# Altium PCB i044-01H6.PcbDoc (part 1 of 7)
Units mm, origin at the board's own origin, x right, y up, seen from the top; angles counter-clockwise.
Board outline 42 x 29.01 mm, 8 copper layers (Top Layer, Mid-Layer 1, Mid-Layer 2, Mid-Layer 3, Mid-Layer 4, Mid-Layer 5, Mid-Layer 6, Bottom Layer), stack 1.474 mm thick; 235 components, 197 nets, 1006 pads, 1183 vias.
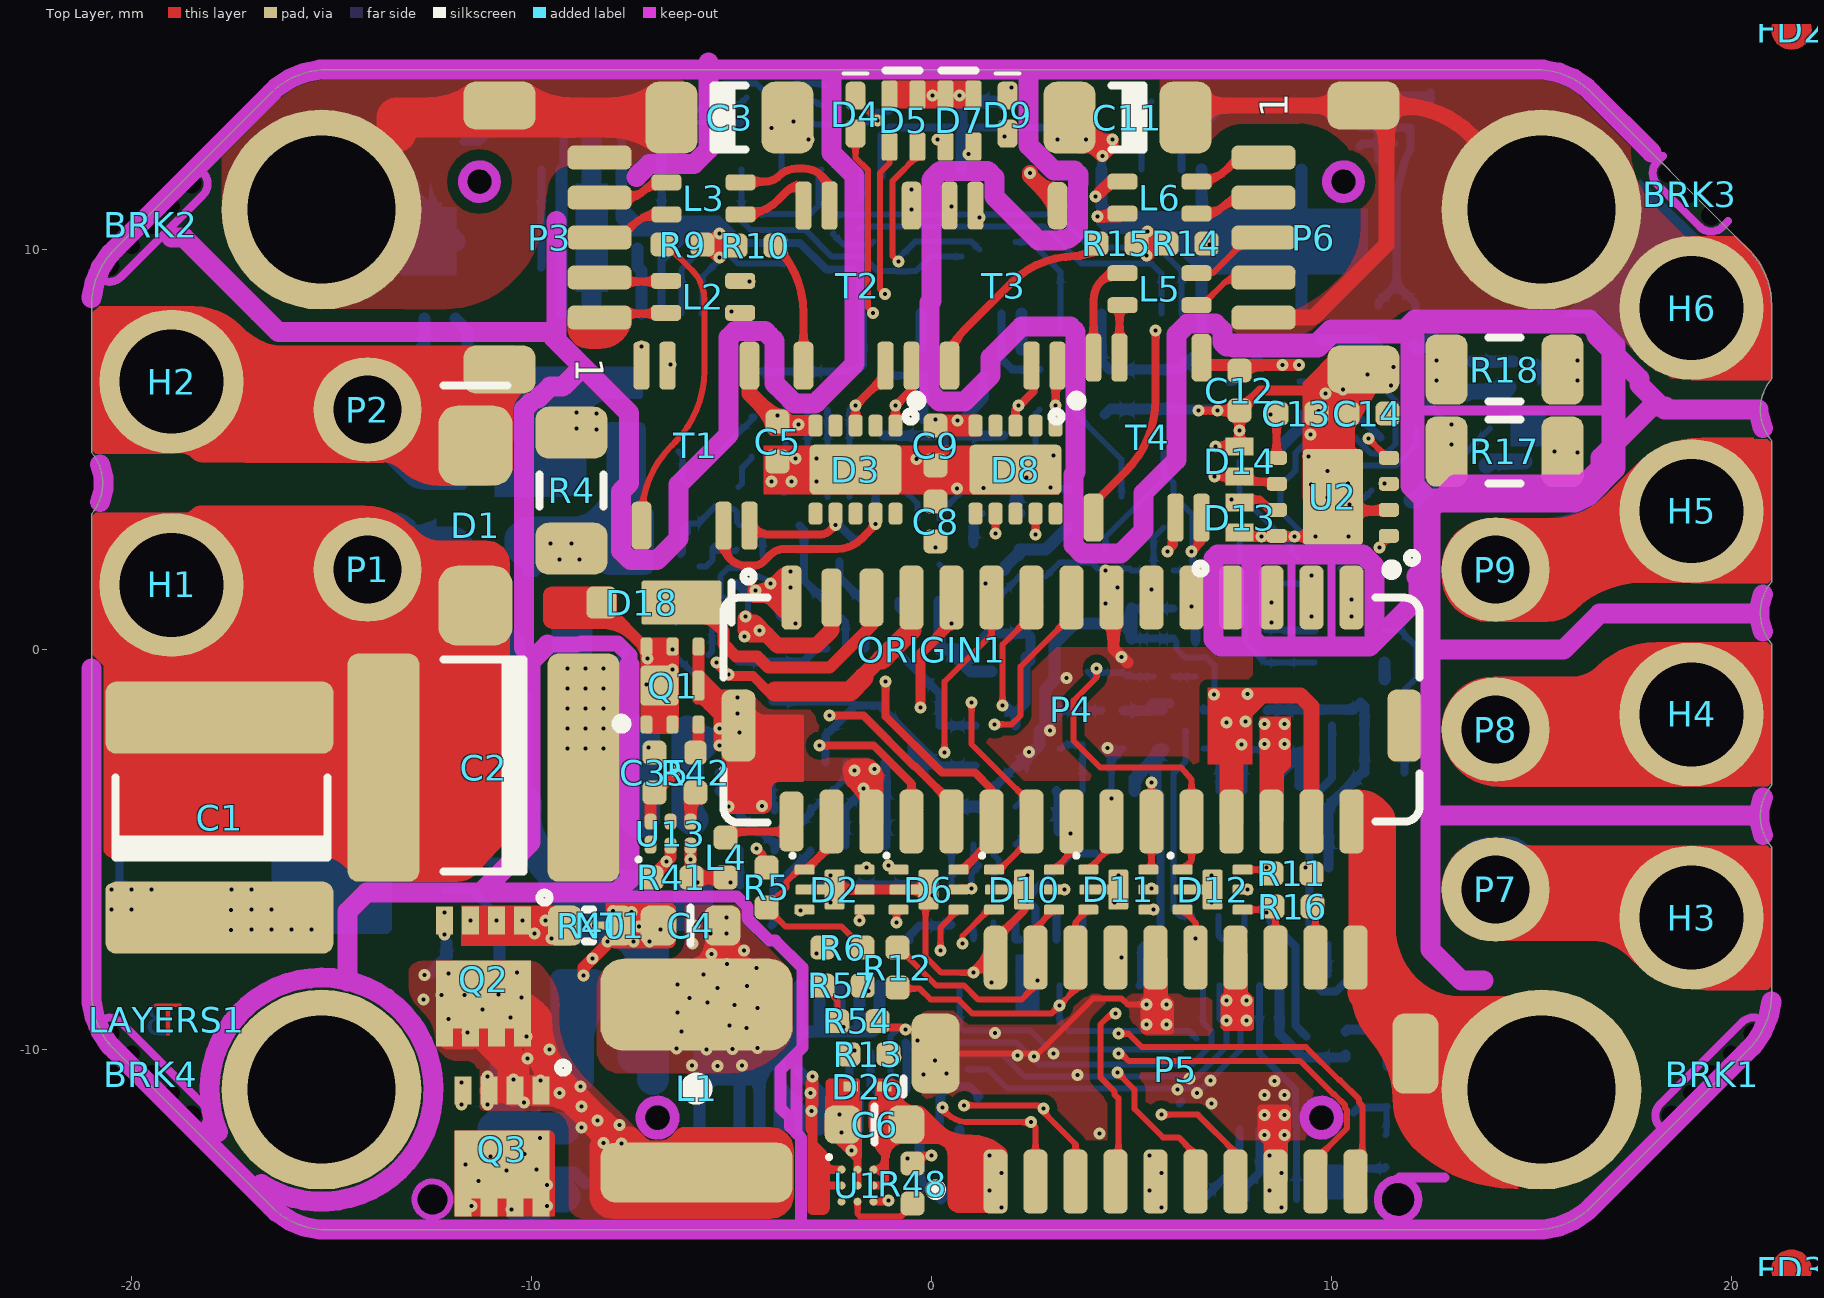
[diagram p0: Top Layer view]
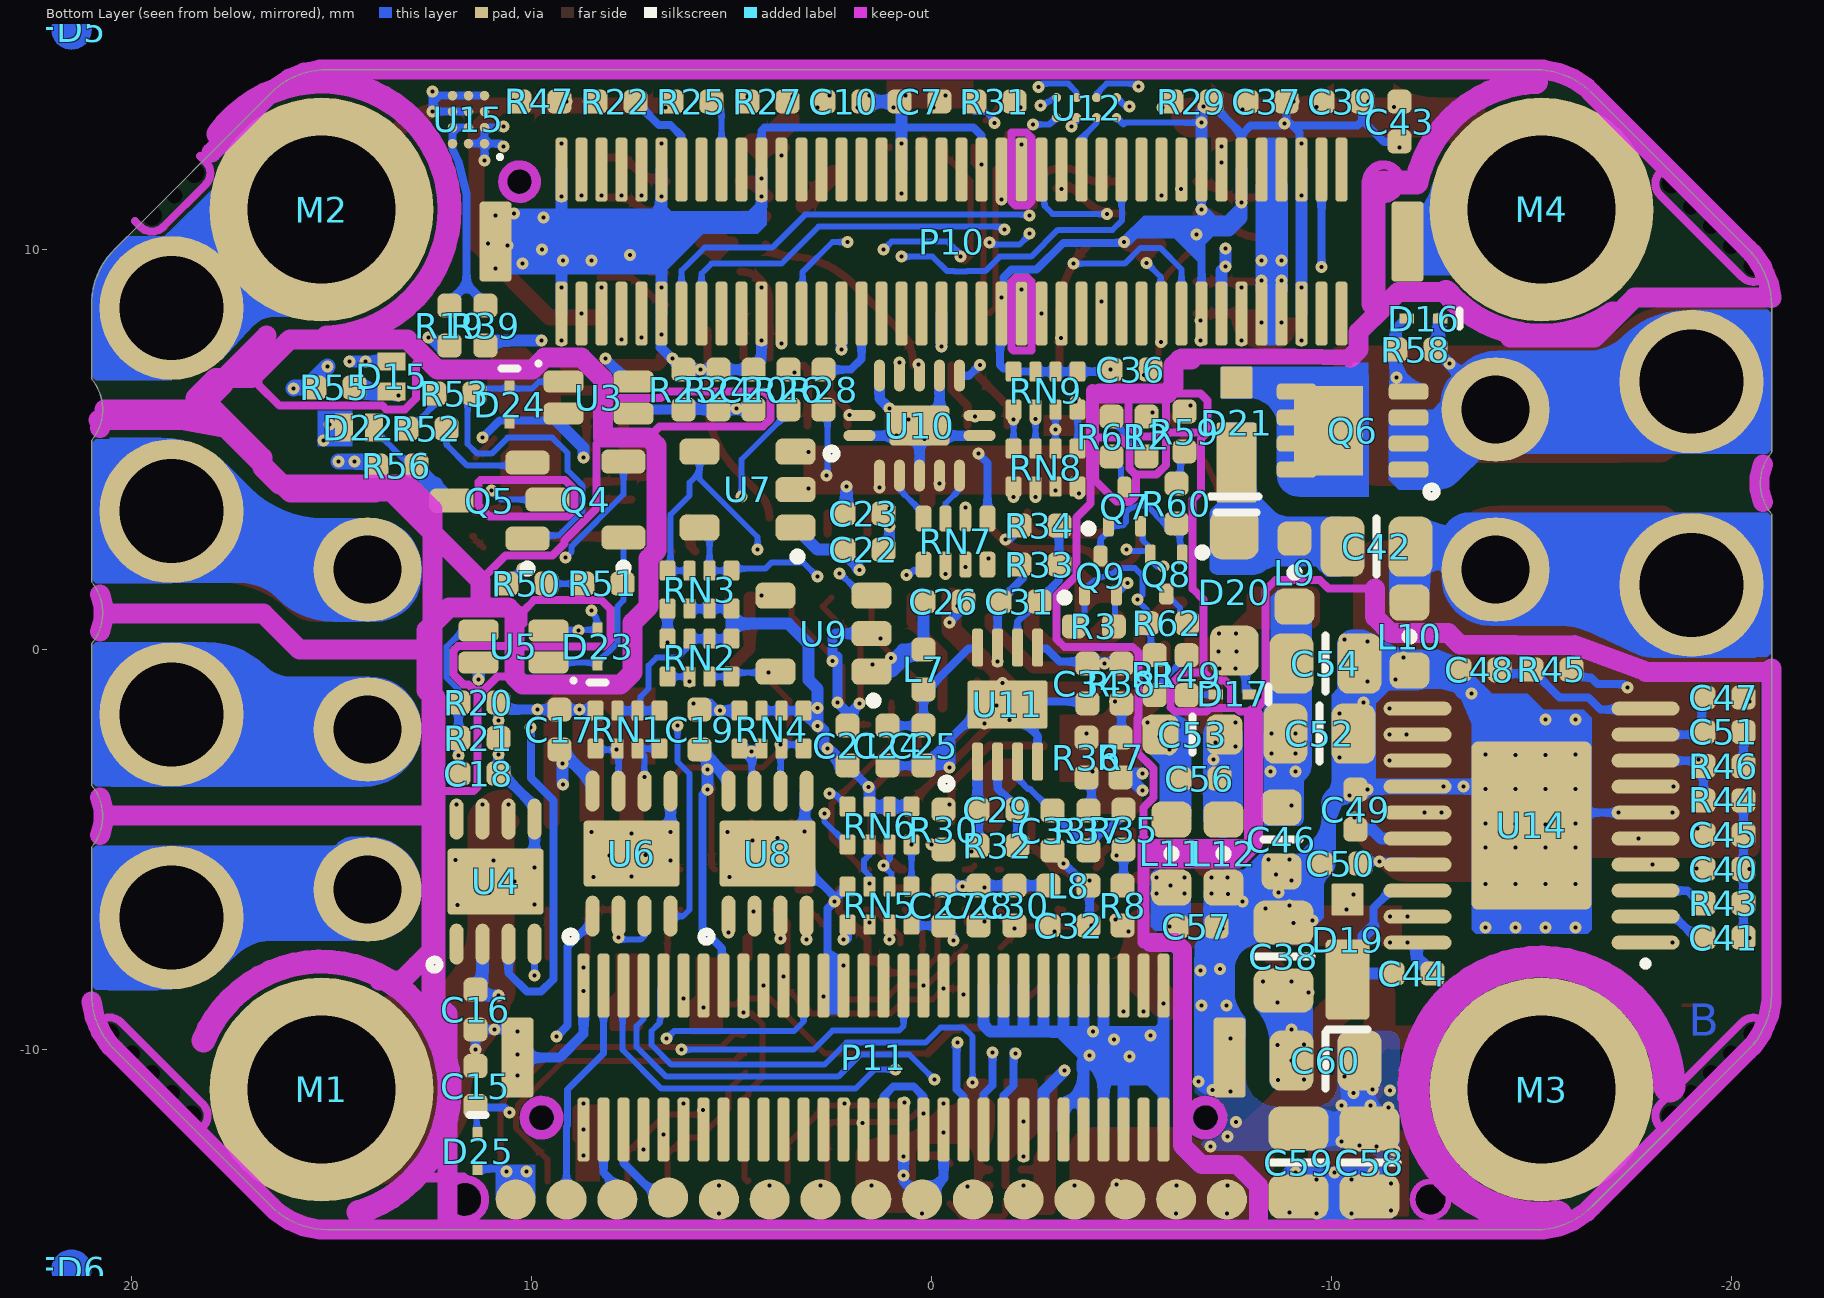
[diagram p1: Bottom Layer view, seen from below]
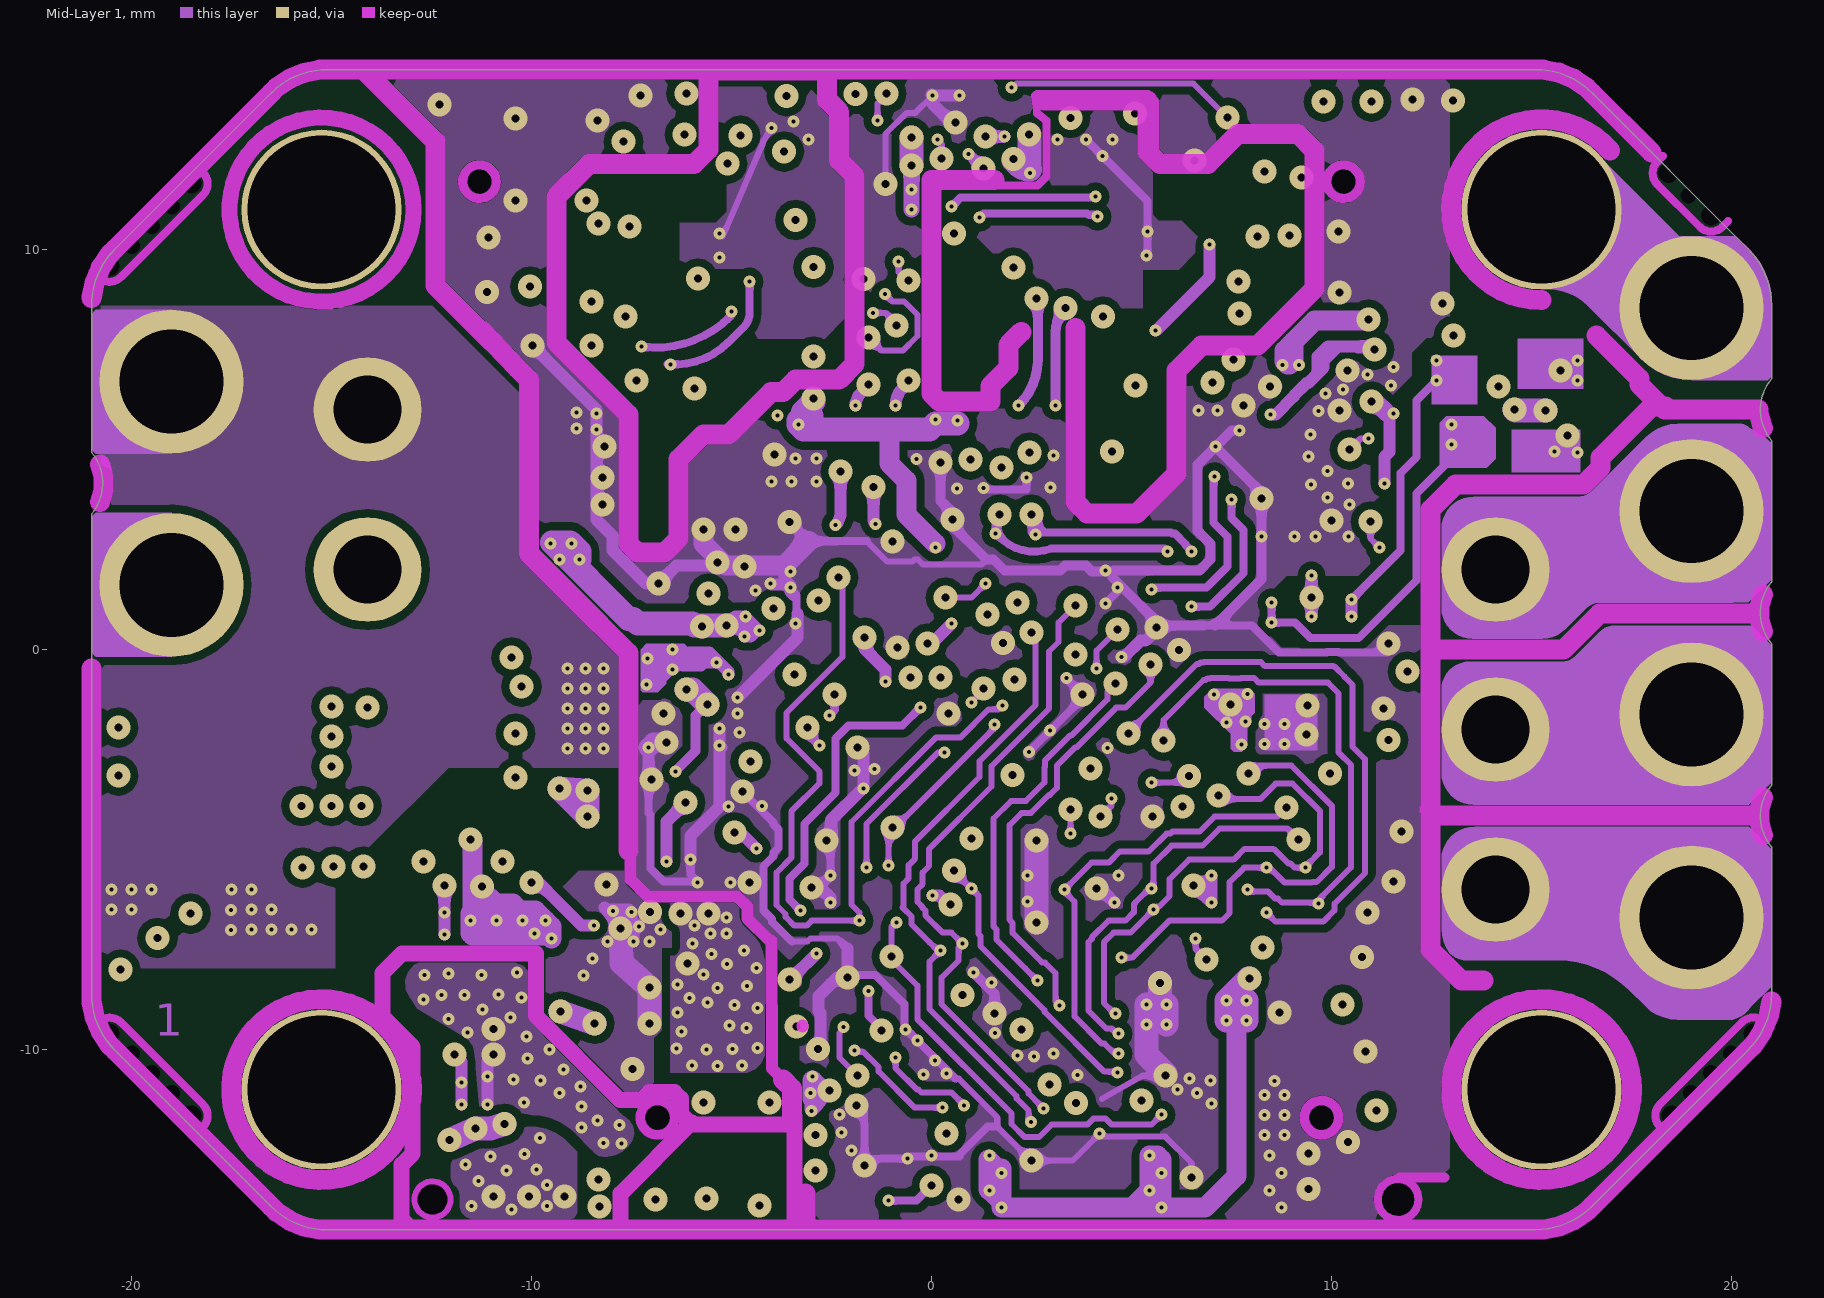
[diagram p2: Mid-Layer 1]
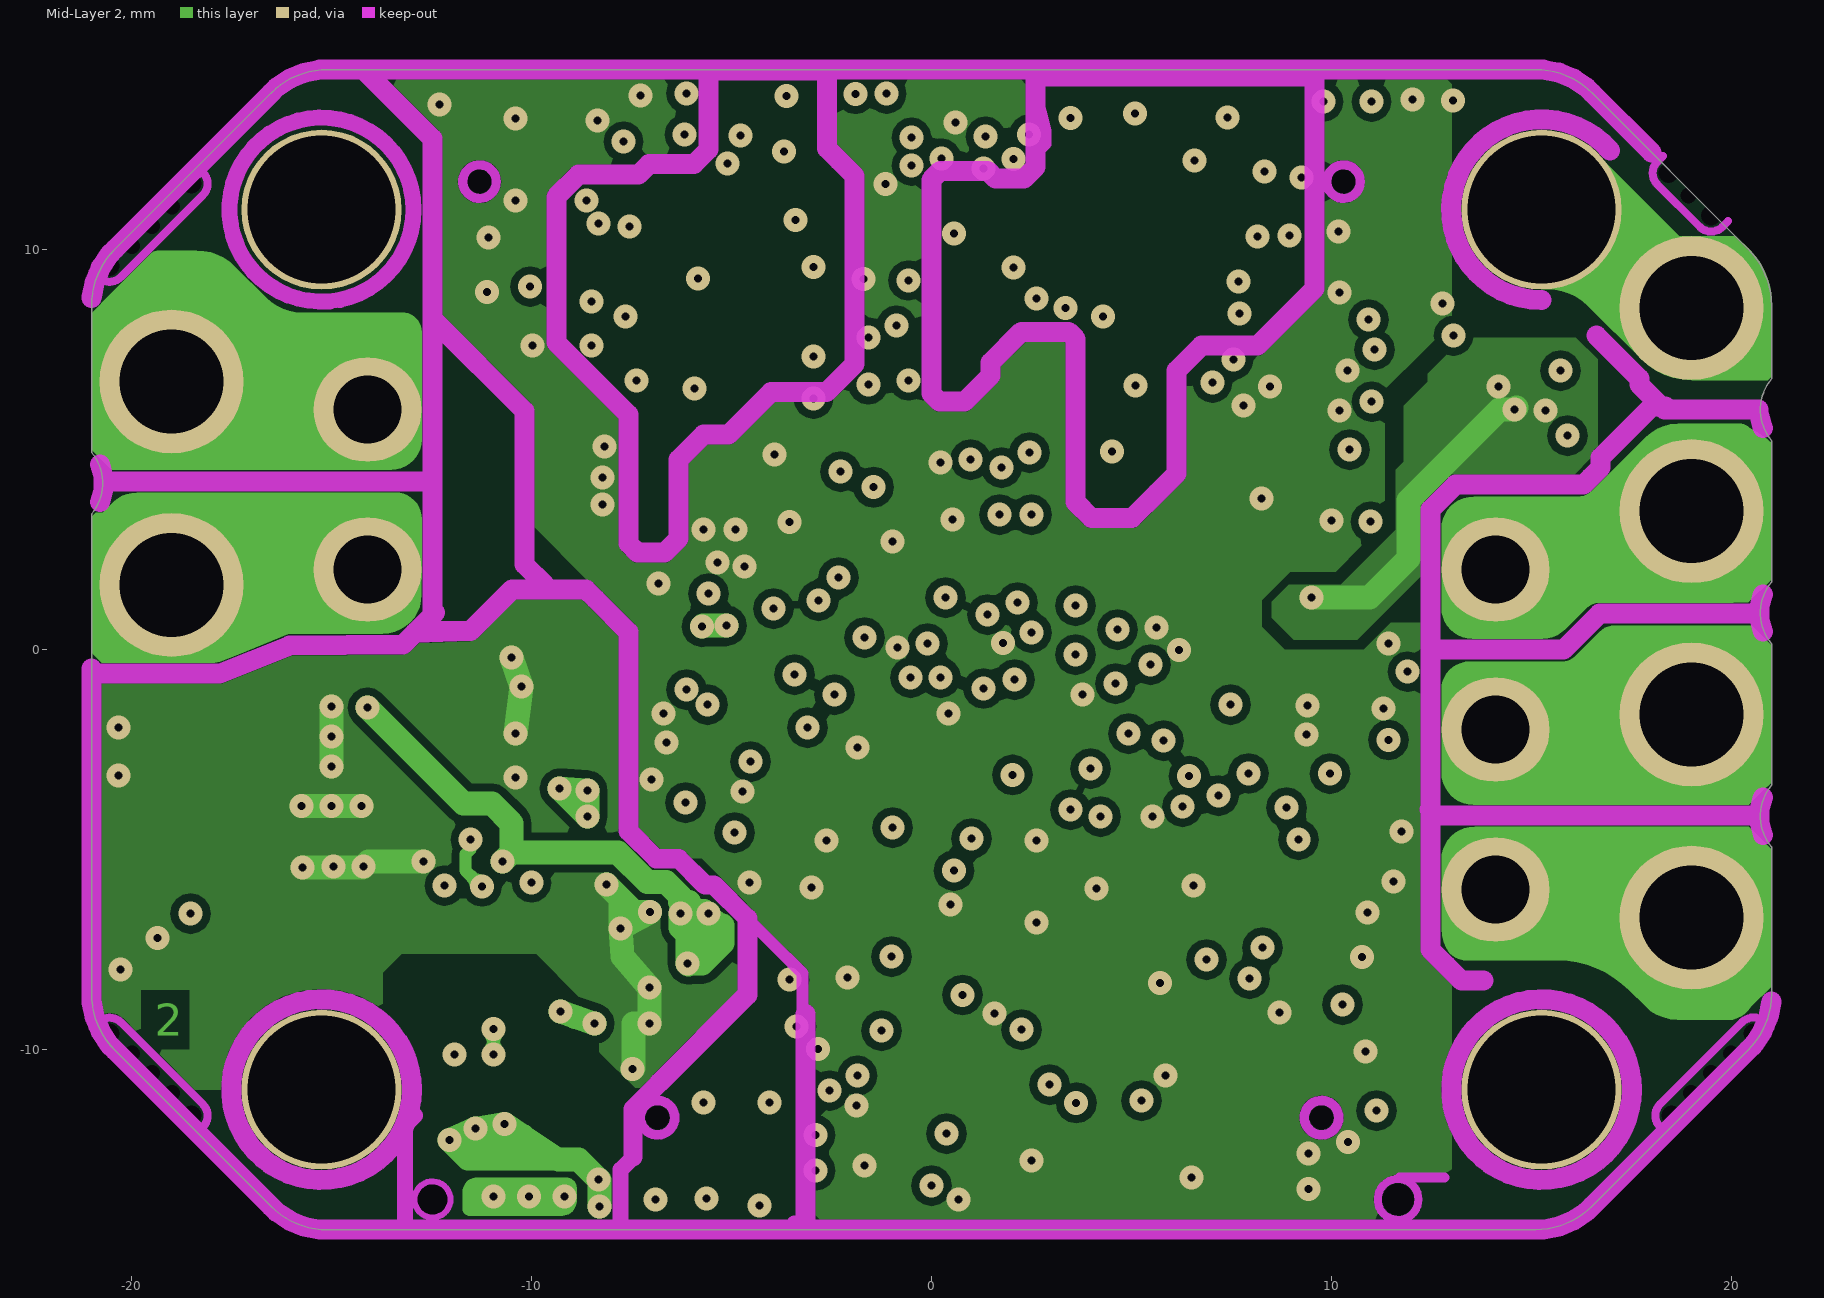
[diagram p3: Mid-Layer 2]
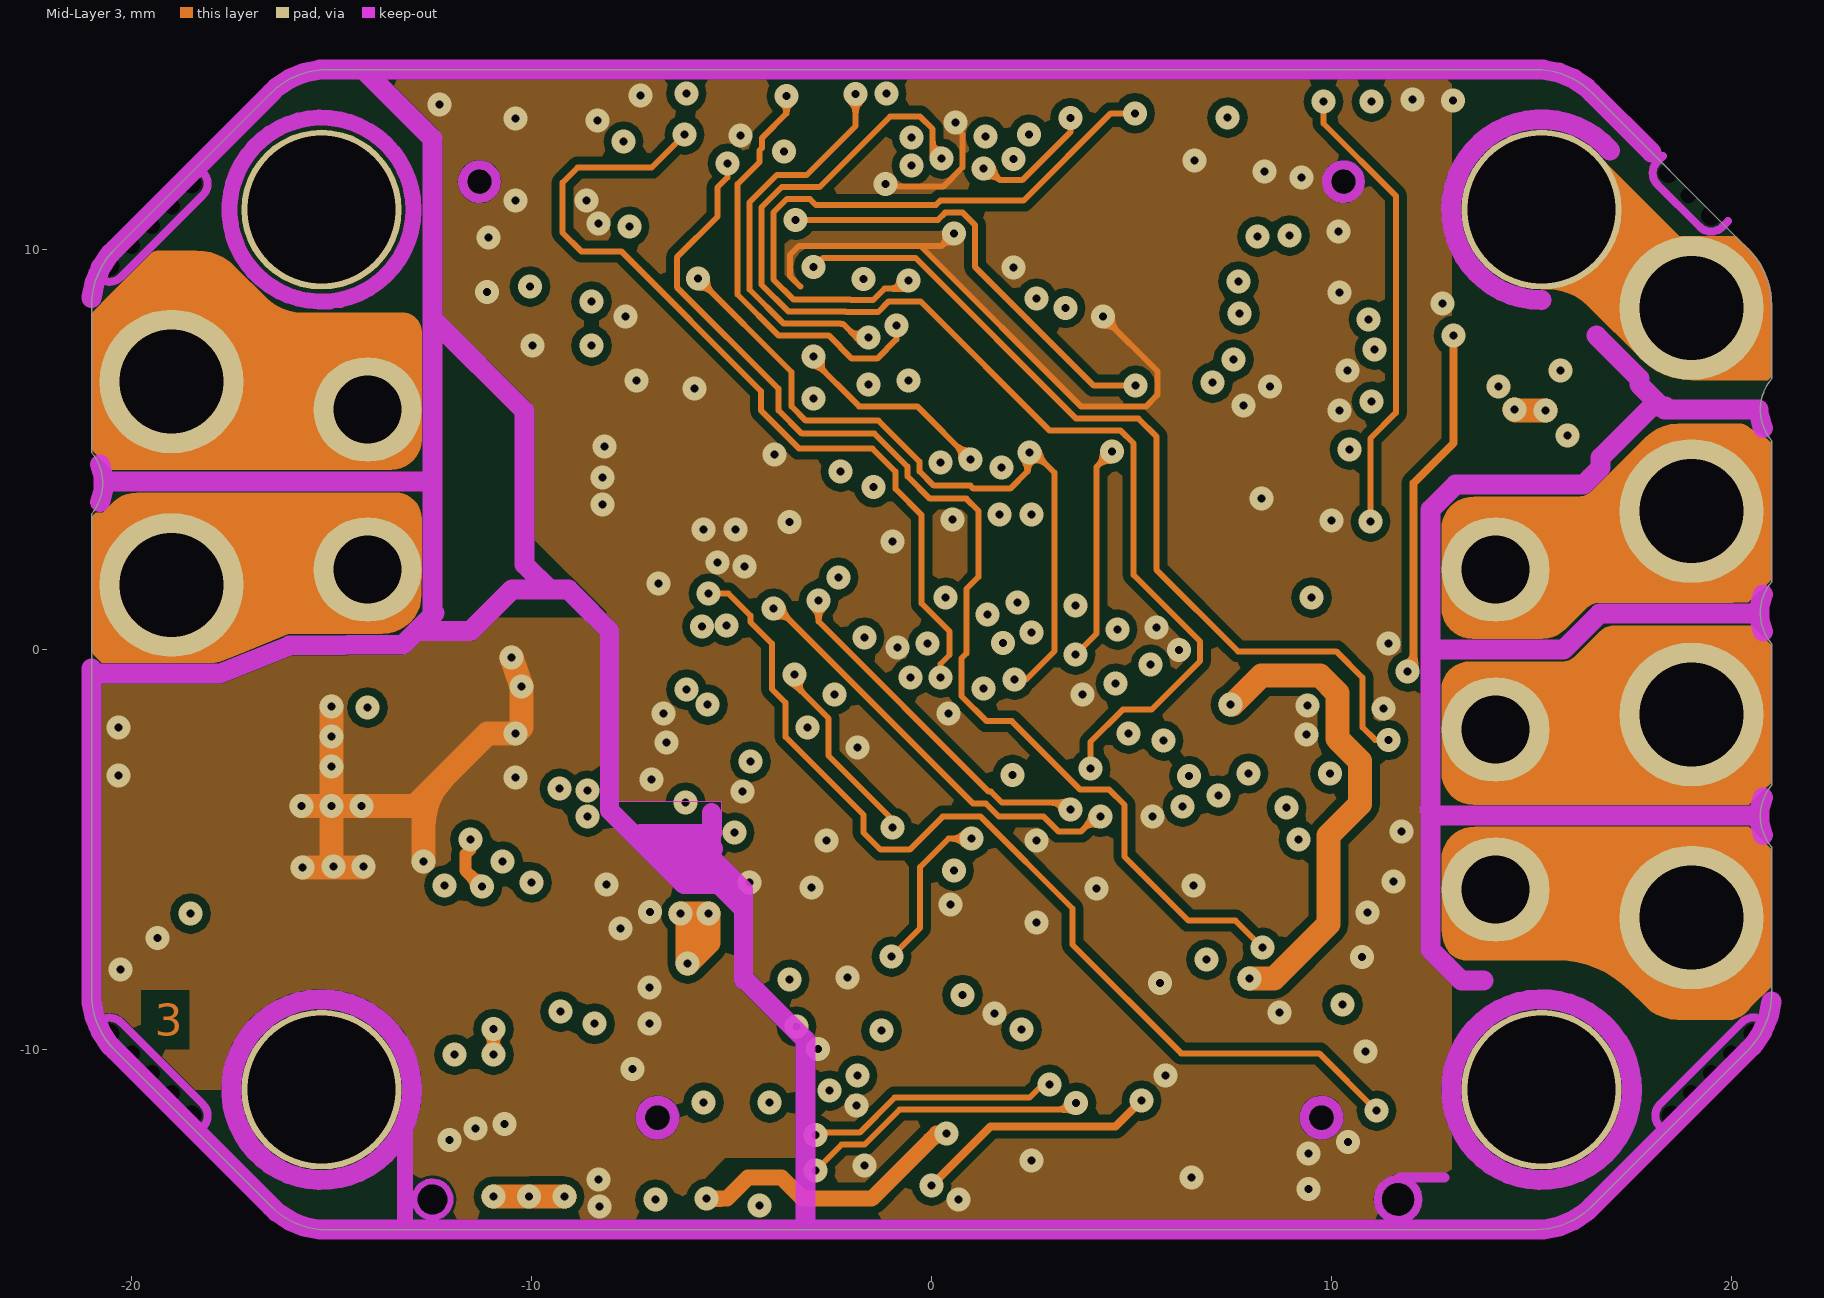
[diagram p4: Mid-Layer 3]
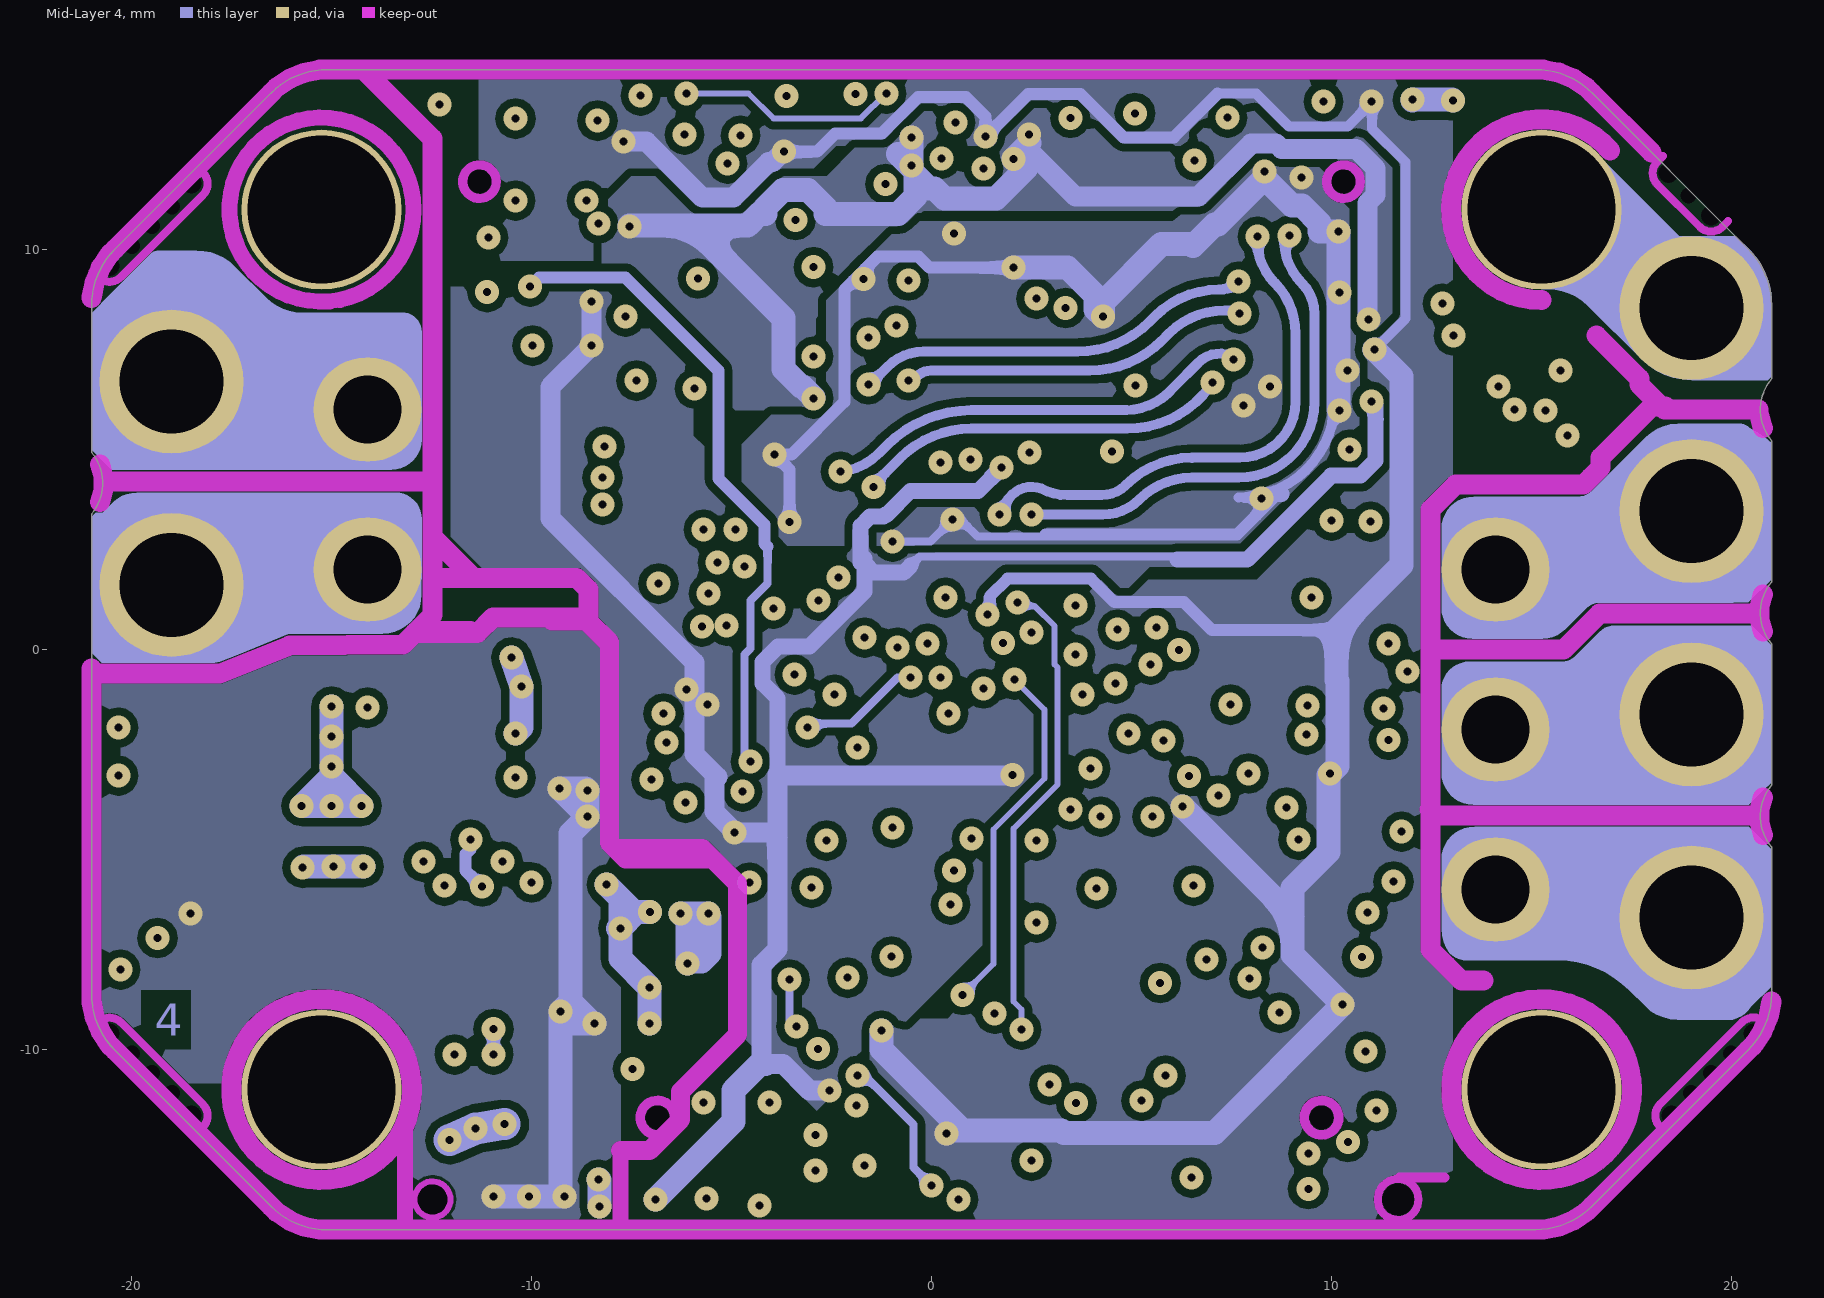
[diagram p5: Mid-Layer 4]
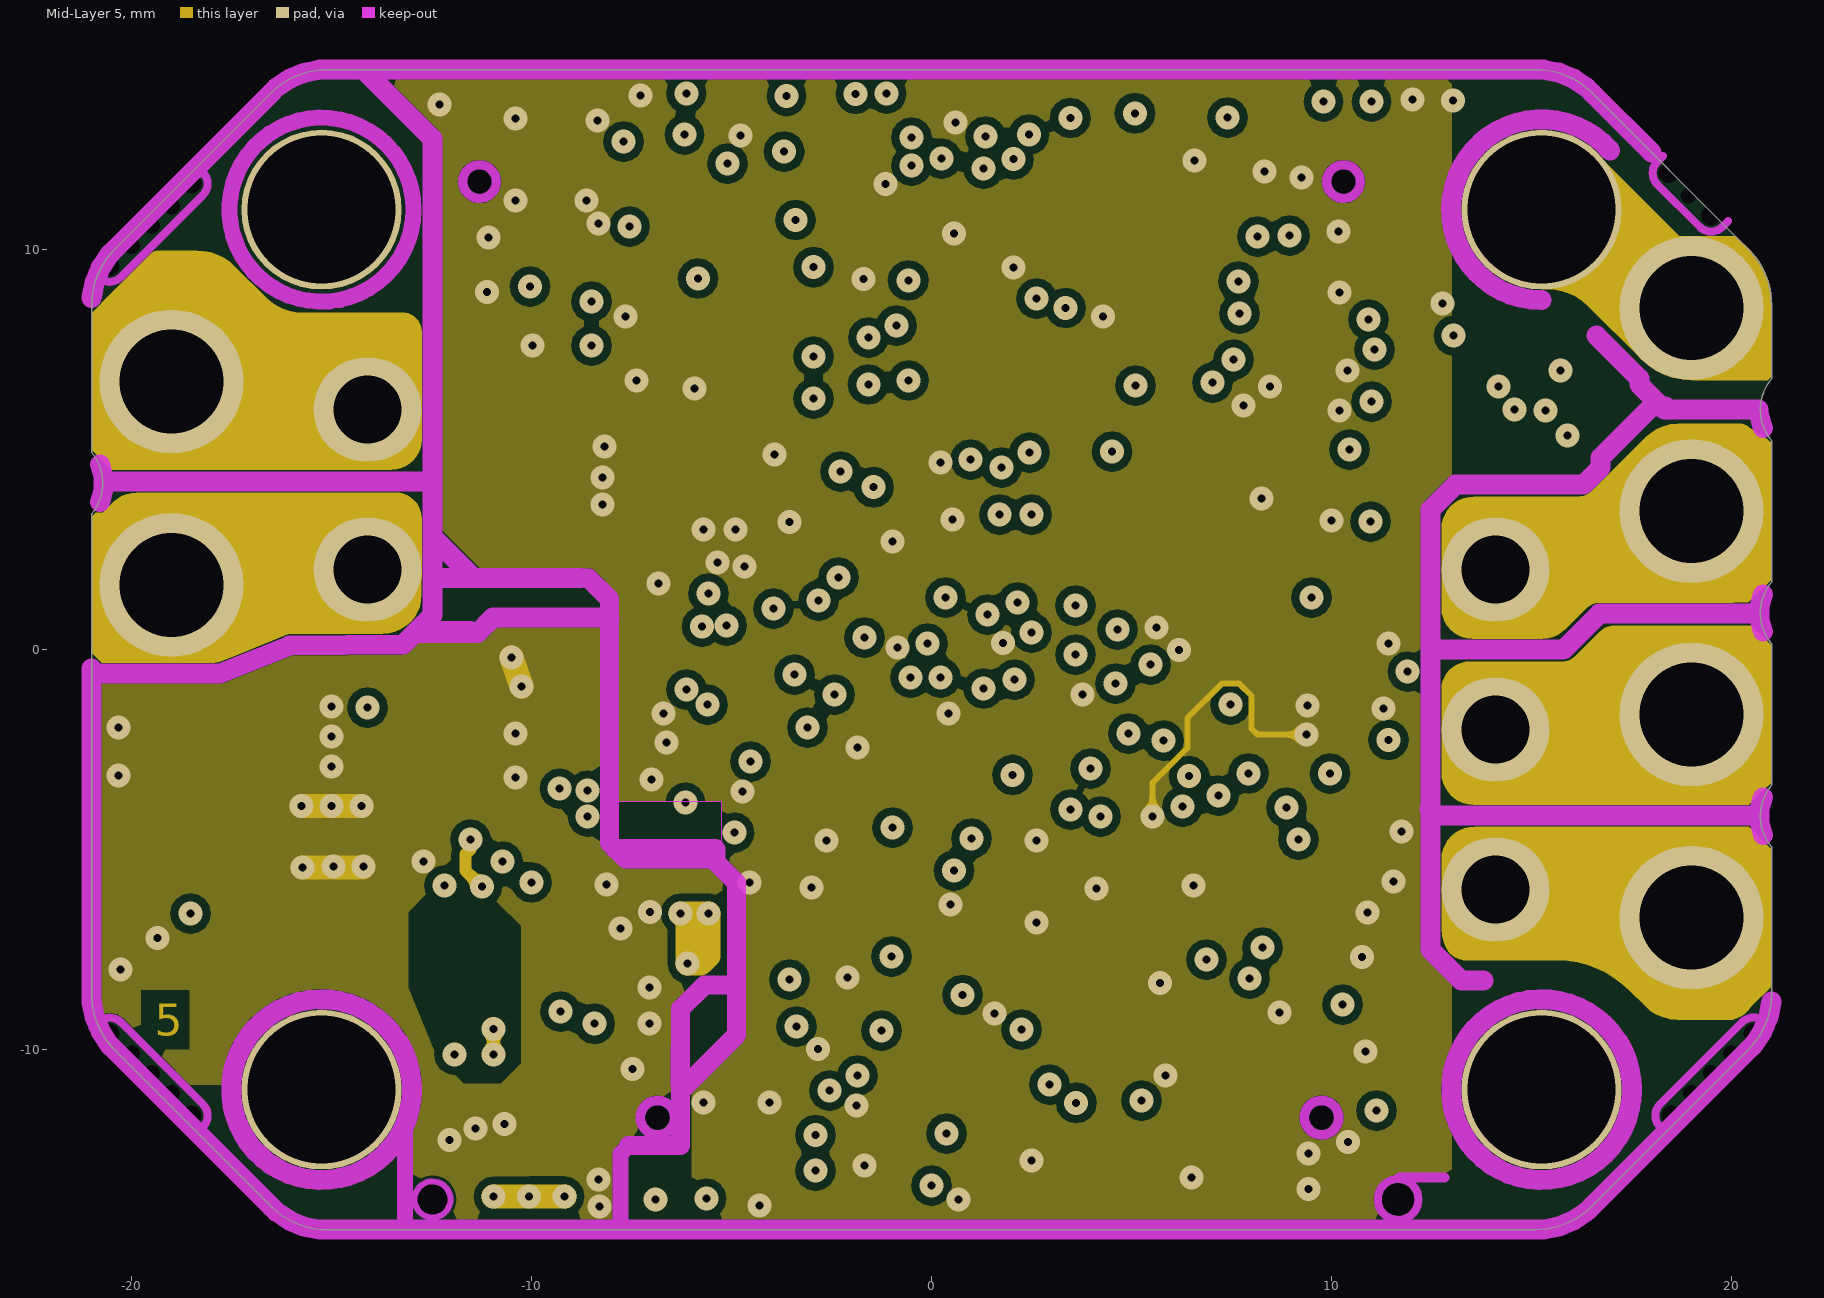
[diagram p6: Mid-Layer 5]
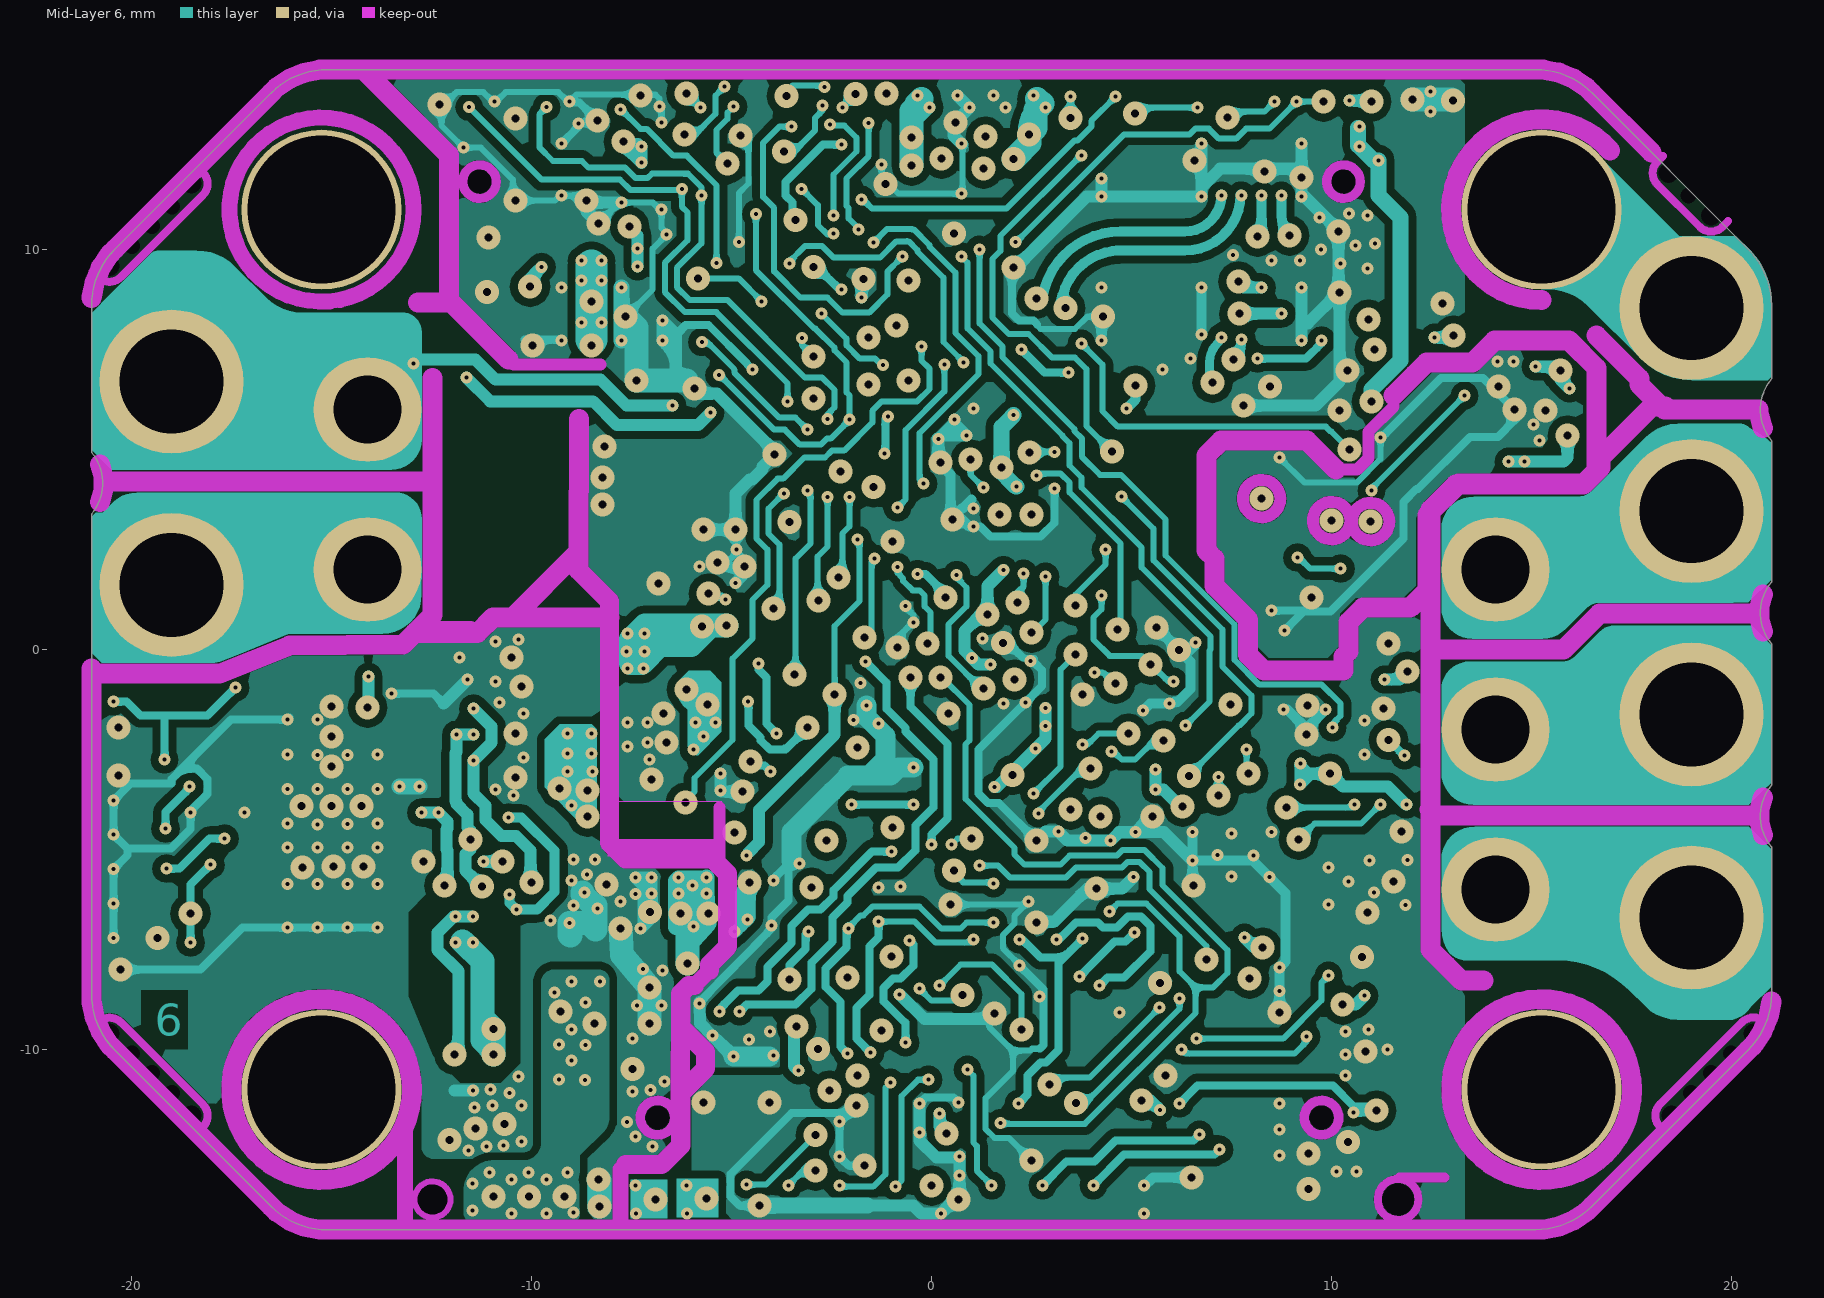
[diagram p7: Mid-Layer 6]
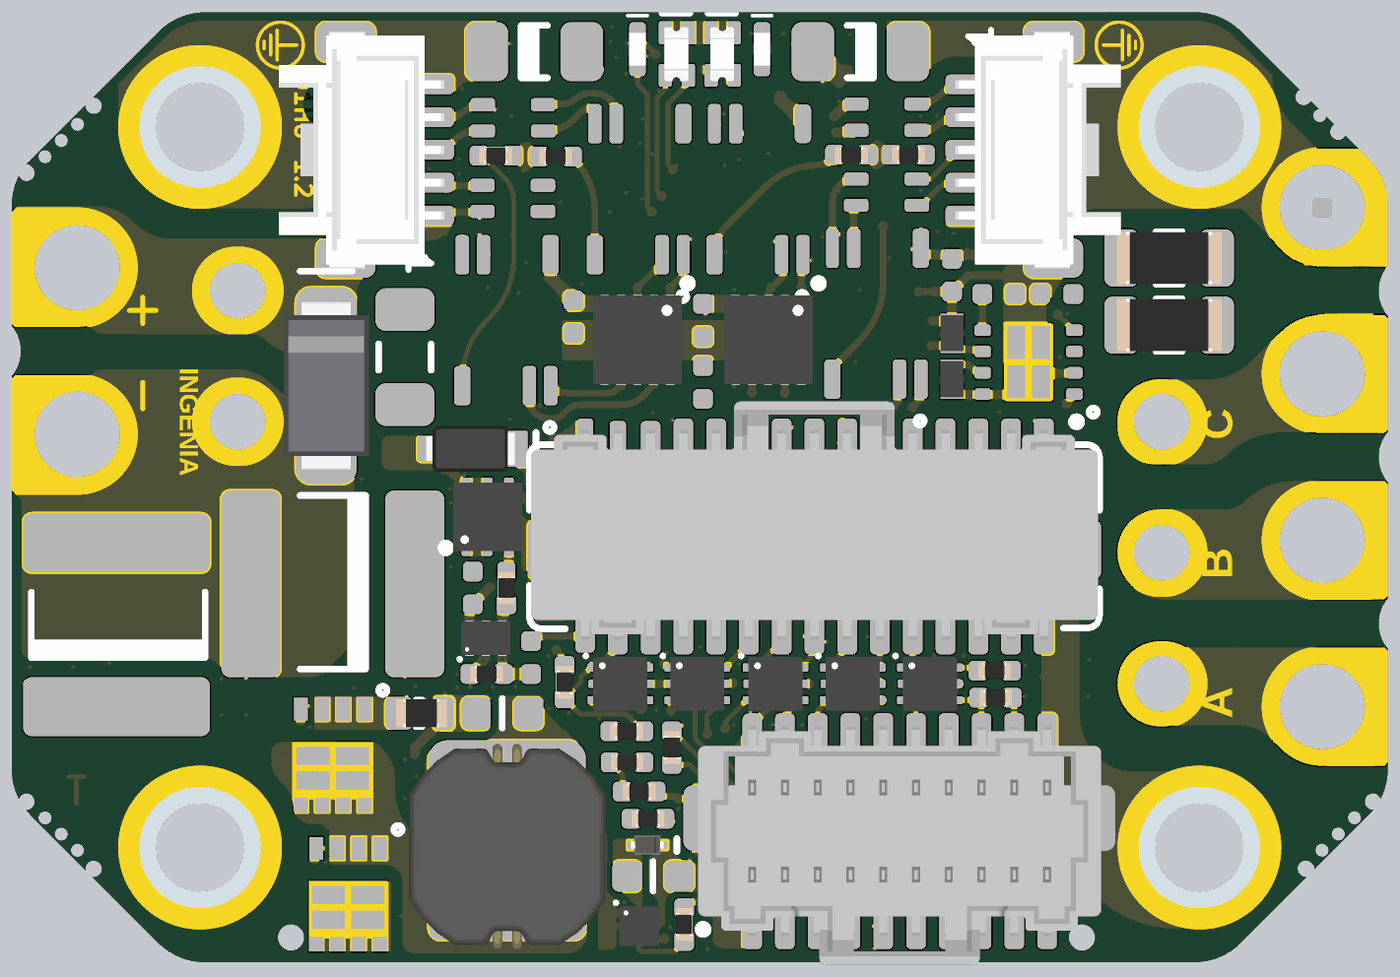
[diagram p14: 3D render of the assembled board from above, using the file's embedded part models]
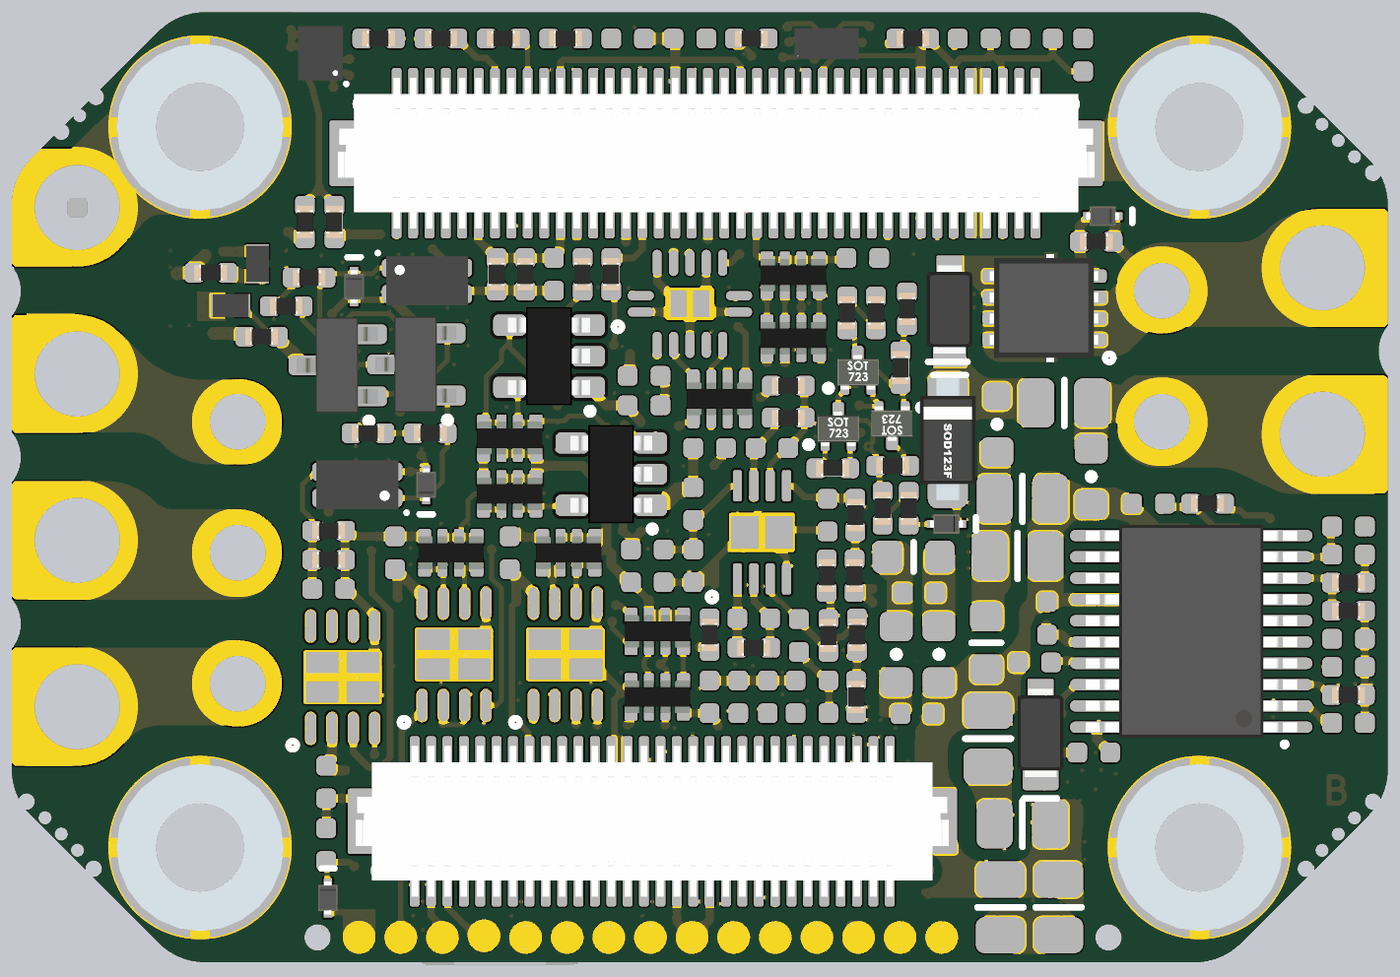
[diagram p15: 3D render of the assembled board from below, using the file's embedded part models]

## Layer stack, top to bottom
Top Solder: solder mask 0.005, Solder Resist, Dk 3.5
Top Layer: signal copper 0.042
Dielectric 1: prepreg 0.1, FR-4 (tg > 150 Celsius), Dk 4.2
Mid-Layer 1: signal copper 0.035
Dielectric 2: core 0.24, FR-4 (tg > 150 Celsius), Dk 4.2
Mid-Layer 2: signal copper 0.035
Dielectric 3: prepreg 0.13, FR-4 (tg > 150 Celsius), Dk 4.2
Mid-Layer 3: signal copper 0.035
Dielectric 4: core 0.24, FR-4 (tg > 150 Celsius), Dk 4.2
Mid-Layer 4: signal copper 0.035
Dielectric 5: prepreg 0.13, FR-4 (tg > 150 Celsius), Dk 4.2
Mid-Layer 5: signal copper 0.035
Dielectric 6: core 0.24, FR-4 (tg > 150 Celsius), Dk 4.2
Mid-Layer 6: signal copper 0.035
Dielectric 7: prepreg 0.1, FR-4 (tg > 150 Celsius), Dk 4.2
Bottom Layer: signal copper 0.042
Bottom Solder: solder mask 0.005, Solder Resist, Dk 3.5

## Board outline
-20.414,-10.017 -16.516,-13.917 ccw(c-15.102,-12.503) -15.102,-14.503 -15.1,-14.502 15.1,-14.498 ccw(c15.1,-12.498) 16.514,-13.913 20.414,-10.014 ccw(c19,-8.6) 21,-8.6 21,-4.933 cw(c21.919,-4.161) 21,-3.39 21,0.147 cw(c21.919,0.919) 21,1.69 21,5.227 cw(c21.919,5.999) 21,6.77 21,8.603 ccw(c19,8.603) 20.414,10.017 16.517,13.915 16.516,13.917 ccw(c15.102,12.503) 15.102,14.503 15.1,14.502 -15.1,14.498 ccw(c-15.1,12.498) -16.514,13.913 -20.414,10.014 ccw(c-19,8.6) -21,8.6 -21,4.932 cw(c-21.919,4.161) -21,3.389 -21,-8.603 ccw(c-19,-8.603)

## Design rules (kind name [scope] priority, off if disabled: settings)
AssemblyTestPointUsage [All] p1 off: valid=2
AssemblyTestpoint [All] p1 off: testpointundercomponent=TRUE minsize=1.016 maxsize=2.54 preferedsize=1.524 minholesize=0 maxholesize=1.016 preferedholesize=0.813 testpointgrid=0.025 usegrid=TRUE gridtolerance=0 allowsidetop=TRUE allowsidebottom=TRUE
Clearance Clearance_BreakAway [HasFootprint('BREAKAWAY_VIAS_3.4MM') Or HasFootprint('BREAKAWAY_VIAS_2MM')] p1: gap=0.01 ignorepadtopadclearanceinfootprint=TRUE
Clearance "Keepout clearance" [All vs OnLayer('Keep-Out Layer') Or IsKeepOut Or Keepout] p2: gap=0.001 ignorepadtopadclearanceinfootprint=FALSE
Clearance HV_Logic_Supply [InNet('+LOG_SUP')] p3: gap=0.2 ignorepadtopadclearanceinfootprint=TRUE
Clearance HV [InNetClass('HighVoltage') vs OnOutside And NOT InNetClass('HighVoltageFloating')] p4: gap=0.5 ignorepadtopadclearanceinfootprint=TRUE
Clearance Clearance_PE [InNetClass('ProtectiveEarth')] p5: gap=0.5 ignorepadtopadclearanceinfootprint=TRUE
Clearance Clearance_Poly [InPoly] p6: gap=0.2 ignorepadtopadclearanceinfootprint=FALSE
Clearance General [All] p7: gap=0.15 ignorepadtopadclearanceinfootprint=TRUE
ComponentClearance PowerPads_Clearance [HasFootprint('PAD_1.65MMTH')] p1: gap=0 collisioncheckmode=3 verticalgap=0 showdistances=FALSE donotcheckwithout3dbody=TRUE
ComponentClearance Fastene_Clearance [IsFree And OnLayer('Mechanical 1')] p2: gap=0 collisioncheckmode=3 verticalgap=0 showdistances=FALSE donotcheckwithout3dbody=TRUE
ComponentClearance Origin_Clearance [HasFootprint('ORIGIN')] p3: gap=0 collisioncheckmode=3 verticalgap=0 showdistances=FALSE donotcheckwithout3dbody=TRUE
ComponentClearance [All] p4: gap=0.2 collisioncheckmode=3 verticalgap=0.2 showdistances=FALSE donotcheckwithout3dbody=TRUE
DiffPairsRouting [All] p1: maxlimit=1 minlimit=0.15 mostfreqgap=0.2 toplayer_minwidth=0.15 toplayer_maxwidth=0.3 toplayer_prefwidth=0.2 midlayer1_minwidth=0.15 midlayer1_maxwidth=0.3 midlayer1_prefwidth=0.2 midlayer2_minwidth=0.15 midlayer2_maxwidth=0.3 midlayer2_prefwidth=0.2 midlayer3_minwidth=0.15 midlayer3_maxwidth=0.3 midlayer3_prefwidth=0.2 midlayer4_minwidth=0.15 midlayer4_maxwidth=0.3 midlayer4_prefwidth=0.2 midlayer5_minwidth=0.15 midlayer5_maxwidth=0.3 midlayer5_prefwidth=0.2 midlayer6_minwidth=0.15 midlayer6_maxwidth=0.3 midlayer6_prefwidth=0.2 bottomlayer_minwidth=0.15 bottomlayer_maxwidth=0.3 bottomlayer_prefwidth=0.2 maxuncoupledlength=12.7
FabricationTestPointUsage [All] p1 off: valid=0 allowmultiple=FALSE
FabricationTestpoint [All] p1 off: side=3 testpointundercomponent=TRUE minsize=1.016 maxsize=2.54 preferedsize=1.524 minholesize=0 maxholesize=1.016 preferedholesize=0.813 testpointgrid=0.025 allowsidetop=TRUE allowsidebottom=TRUE usegrid=TRUE gridtolerance=0
FanoutControl Fanout_BGA [IsBGA] p1 off: bgadir=Out bgaviamode=Centered fanoutstyle=Auto fanoutdirection=Alternating viagrid=0.025 // Fanout_BGA (Default Rule)
FanoutControl Fanout_LCC [IsLCC] p2 off: bgadir=Out bgaviamode=Centered fanoutstyle=Auto fanoutdirection=Alternating viagrid=0.025 // Fanout_LCC (Default Rule)
FanoutControl Fanout_SOIC [IsSOIC] p3 off: bgadir=Out bgaviamode=Centered fanoutstyle=Auto fanoutdirection=Alternating viagrid=0.025 // Fanout_SOIC (Default Rule)
FanoutControl Fanout_Small [(CompPinCount < 5)] p4 off: bgadir=Out bgaviamode=Centered fanoutstyle=Auto fanoutdirection=OutThenIn viagrid=0.025 // Fanout_Small (Default Rule)
FanoutControl Fanout_Default [All] p5 off: bgadir=Out bgaviamode=Centered fanoutstyle=Auto fanoutdirection=Alternating viagrid=0.025 // Fanout_Default (Default Rule)
Height [All] p1: minheight=0 maxheight=30 prefheight=12.7
HoleSize [All] p1: absolutevalues=TRUE maxlimit=5 minlimit=0.1 maxpercent=80.000 minpercent=20.000
HoleToHoleClearance [All] p1: gap=0.3 allowstackedmicrovias=FALSE
MinimumAnnularRing [All] p1: minimumring=0.1
MinimumSolderMaskSliver [All] p1: minsoldermaskwidth=0.07
NetAntennae [All] p1: netantennaetolerance=2
PlaneClearance [All] p1: clearance=0.25
PlaneConnect [All] p1: planeconnectstyle=Relief reliefexpansion=0.5 reliefentries=4 reliefconductorwidth=0.25 reliefairgap=0.25
PolygonConnect [All] p1: connectstyle=Direct reliefconductorwidth=0.25 reliefentries=4 polygonreliefangle="90 Angle" airgapwidth=0.25
RoomDefinition U_M_PXE032_HD_Diff-SE_Digital_Abs_Encoder_WBias_WTerm [InComponentClass('U_M_PXE032_HD_Diff-SE_Digital_Abs_Encoder_WBias_WTerm')] p1 off: confinementstyle=ConfineIn formatcopy=TRUE lockcomponents=FALSE outline 22.12,-5.98 65.62,-5.98 65.62,-0.98 22.12,-0.98
RoomDefinition U_M_IEA007_EHT1 [InComponentClass('U_M_IEA007_EHT1')] p2 off: confinementstyle=ConfineIn formatcopy=TRUE lockcomponents=FALSE outline 22.12,73.42 43.32,73.42 43.32,78.62 22.12,78.62
RoomDefinition U_M_IEA007_EHT0 [InComponentClass('U_M_IEA007_EHT0')] p3 off: confinementstyle=ConfineIn formatcopy=TRUE lockcomponents=FALSE outline 22.12,66.92 43.32,66.92 43.32,72.22 22.12,72.22
RoomDefinition U_M_ICA011_HDI_CAN_Interface_NonIsolated_5Vsupply [InComponentClass('U_M_ICA011_HDI_CAN_Interface_NonIsolated_5Vsupply')] p4 off: confinementstyle=ConfineIn formatcopy=TRUE lockcomponents=FALSE outline 22.12,23.42 32.62,23.42 32.62,28.42 22.12,28.42
RoomDefinition U_M_GAI020_HD_Diff_In_Diff_Out+-10V_AnalogInput_3V3REF [InComponentClass('U_M_GAI020_HD_Diff_In_Diff_Out+-10V_AnalogInput_3V3REF')] p5 off: confinementstyle=ConfineIn formatcopy=TRUE lockcomponents=FALSE outline 22.12,10.82 56.32,10.82 56.32,13.92 22.12,13.92
RoomDefinition U_M_FMS007_Optocoupled_input_STO_SIL3_Compliant [InComponentClass('U_M_FMS007_Optocoupled_input_STO_SIL3_Compliant')] p6 off: confinementstyle=ConfineIn formatcopy=TRUE lockcomponents=FALSE outline 22.22,-6.08 80.72,-6.08 80.72,3.72 22.22,3.72
RoomDefinition U_M_SSD128_HD_8_95Vin_5Vout_1500mA_LowProfile [InComponentClass('U_M_SSD128_HD_8_95Vin_5Vout_1500mA_LowProfile')] p7 off: confinementstyle=ConfineIn formatcopy=TRUE lockcomponents=FALSE outline 23.627,-3.275 72.63,-3.275 72.63,3.5 23.627,3.5
RoomDefinition U_M_PXA001_HDI_BiSS_SSI_EnDAT_AbsoluteEncoder [InComponentClass('U_M_PXA001_HDI_BiSS_SSI_EnDAT_AbsoluteEncoder')] p8 off: confinementstyle=ConfineIn formatcopy=TRUE lockcomponents=FALSE outline 23.627,-5.775 339.118,-5.775 339.118,5.15 23.627,5.15
RoomDefinition Top [InComponentClass('Top')] p9 off: confinementstyle=ConfineIn formatcopy=TRUE lockcomponents=FALSE outline -129.38,-99.68 -78.58,-99.68 -78.58,-74.28 -129.38,-74.28
RoutingVias [All] p1: holewidth=0.2 width=0.6 viastyle="Through Hole" minholewidth=0.1 minwidth=0.3 maxholewidth=1 maxwidth=1.5
SilkToSilkClearance [All] p1 off: silktosilkclearance=0.1
SilkToSolderMaskClearance SilkscreenOverComponentPads [IsPad] p1 off: minsilkscreentomaskgap=0.05 clearancetoexposedcopper=TRUE
SolderMaskExpansion [All] p1: expansion=0.05 istentingtop=FALSE
UnRoutedNet [All] p1: checkbadconnections=TRUE
Width [All] p1: maxlimit=80 minlimit=0.15 preferedwidth=0.2 checkconnectedcopper=TRUE
9 further rules are at their usual default settings.

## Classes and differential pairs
net class Iso: NetC3_2 NetC11_2 NetL2_3 NetL2_4 NetL3_3 NetL3_4 NetL5_3 NetL5_4 NetL6_3 NetL6_4 NetR9_2 NetR10_1 NetR14_1 NetR15_2
net class HighVoltageFloating: NetD16_1
channel class M_IEA007_HDI_EtherNet_Discrete_Magnetics+ESD: U_M_IEA007_EHT0 U_M_IEA007_EHT1
component class U_M_PXE032_HD_Diff-SE_Digital_Abs_Encoder_WBias_WTerm: C16 C17 C21 C26 R11 R12 R13 R65 RN1 RN2 RN3 U6 U7 U9
component class U_M_PXA001_HDI_BiSS_SSI_EnDAT_AbsoluteEncoder: C19 C22 R16 RN4 U4 U8
component class U_M_IEA007_EHT1: C9 C10 C11 C12 L5 L6 R14 R15 T3 T4
component class U_M_IEA007_EHT0: C3 C5 C7 C8 L2 L3 R9 R10 T1 T2
component class U_M_ICA011_HDI_CAN_Interface_NonIsolated_5Vsupply: C13 C14 U2
component class U_M_GAI020_HD_Diff_In_Diff_Out+-10V_AnalogInput_3V3REF: C24 C25 C29 C31 C33 C34 L7 R30 R32 R33 R34 R35 R36 R37 R38 U11 U22
component class U_M_FMS007_Optocoupled_input_STO_SIL3_Compliant: C18 C20 D15 D22 D23 D24 Q4 Q5 R17 R18 R19 R20 R21 R23 R24 R39 R50 R51 R52 R53 R55 R56 U3 U5
net class STO: 5V_SAFE \STO1 \STO2 STO1_IN STO2_IN STO_RET
net class HighVoltage: +LOG_SUP +LOGIC_PROTECTED +V_BUS GND_P PH_A PH_B PH_C
net class HighCurrent: +V_BUS GND_P PH_A PH_B PH_C
component class U_M_SSD128_HD_8_95Vin_5Vout_1500mA_LowProfile: C4 C38 C40 C41 C44 C45 C46 C47 C48 C49 C50 C51 C52 C54 C58 C59 C60 D19 L1 NT1 Q2 Q3 R40 R43 R44 R45 R46 U14
component class Top: BRK1 BRK2 BRK3 BRK4 C1 C2 C6 C15 C23 C27 C28 C30 C32 C35 C36 C37 C39 C42 C43 C53 C56 C57 D1 D2 D3 D4 D5 D6 D7 D8 D9 D10 D11 D12 D13 D14 D16 D17 D18 D20 D21 D25 D26 FD1 FD2 FD3 FD4 FD5 FD6 FD7 FD8 FD9 FD10 H1 H2 H3 H4 H5 H6 H9 H10 H11 L4 L8 L9 L10 L11 L12 LABEL1 LAYERS1 M1 M2 M3 M4 ORIGIN1 P1 P2 P3 P4 P5 P6 P7 P8 P9 P10 P11 P? Q1 Q6 Q7 Q8 Q9 R1 R2 R3 R4 R5 R6 R7 R8 R22 R25 R26 R27 R28 R29 R31 R41 R42 R47 R48 R49 R54 R57 R58 R59 R60 R61 R62 RN5 RN6 RN7 RN8 RN9 U1 U10 U12 U13 U15
net class ProtectiveEarth: PE PE1 PE2 PE3
differential pair ENC_Z_IN/CLK_OUT: +ENC_Z_IN/CLK_OUT_P -ENC_Z_IN/CLK_OUT_N
differential pair ENC_B_IN: +ENC_B_IN_P -ENC_B_IN_N
differential pair ENC_A/DATA_IN: +ENC_A/DATA_IN_P -ENC_A/DATA_IN_N
differential pair PHY1_TX: +PHY1_TX_P -PHY1_TX_N
differential pair PHY1_RX: +PHY1_RX_P -PHY1_RX_N
differential pair PHY0_TX: +PHY0_TX_P -PHY0_TX_N
differential pair PHY0_RX: +PHY0_RX_P -PHY0_RX_N
differential pair ETH1_TX: +ETH1_TX_P -ETH1_TX_N
differential pair ETH1_RX: +ETH1_RX_P -ETH1_RX_N
differential pair ETH0_TX: +ETH0_TX_P -ETH0_TX_N
differential pair ETH0_RX: +ETH0_RX_P -ETH0_RX_N
differential pair ABSENC_DATA: +ABSENC_DATA_P -ABSENC_DATA_N
differential pair ABSENC_CLK: +ABSENC_CLK_P -ABSENC_CLK_N

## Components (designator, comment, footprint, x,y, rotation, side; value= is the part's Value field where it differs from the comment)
BRK1 "BreakAway_Vias_3mm" BREAKAWAY_VIAS_3.4MM 19.664,-10.763 r225 top net-tie value=-
BRK2 "BreakAway_Vias_3mm" BREAKAWAY_VIAS_3.4MM -19.664,10.763 r45 top locked net-tie value=-
BRK3 "BreakAway_Vias_2mm" BREAKAWAY_VIAS_2MM 19.1,11.525 r315 top net-tie value=-
BRK4 "BreakAway_Vias_3mm" BREAKAWAY_VIAS_3.4MM -19.664,-10.767 r135 top locked net-tie value=-
C1 "C_2420_2STACK--15uF--100V/X7R" C_J-LEAD_2STACK_6.1X5.3MM -17.8,-4.2 r90 top value=15uF (schematic designator C2)
C2 "C_2420_2STACK--15uF--100V/X7R" C_J-LEAD_2STACK_6.1X5.3MM -11.2,-2.95 r180 top value=15uF (schematic designator C3)
C3 "C_1206--1000pF--2000V" C_1206 -5.05,13.3 r0 top value=1000pF (schematic designator C5)
C4 "C_0603--10uF--10V/X7T" C_0603#1 -6.025,-6.9 r0 top value=10uF (schematic designator C9)
C5 "C_0402--100nF--16V" C_0402HD -3.85,5.2 r270 top value=100nF (schematic designator C4)
C6 "C_0603--10uF--10V/X7T" C_0603#2 -1.425,-11.875 r0 top value=10uF (schematic designator C8)
C7 "C_0402--100nF--16V" C_0402HD 0.3,13.7 r0 bottom value=100nF (schematic designator C2)
C8 "C_0402--1uF--10V" C_0402HD 0.1,3.2 r270 top value=1uF (schematic designator C1)
C9 "C_0402--1uF--10V" C_0402HD 0.1,5.1 r90 top value=1uF (schematic designator C1)
C10 "C_0402--100nF--16V" C_0402HD 2.2,13.7 r180 bottom value=100nF (schematic designator C4)
C11 "C_1206--1000pF--2000V" C_1206 4.9,13.3 r180 top locked value=1000pF (schematic designator C5)
C12 "C_0402--100nF--16V" C_0402HD 7.7,6.475 r270 top value=100nF (schematic designator C2)
C13 "C_0402--100nF--16V" C_0402HD 9.125,5.9 r180 top value=100nF (schematic designator C2)
C14 "C_0402--100nF--16V" C_0402HD 10.9,5.9 r0 top value=100nF (schematic designator C1)
C15 "C_0402--100nF--16V" C_0402HD 11.4,-10.91 r270 bottom value=100nF (schematic designator C16)
C16 "C_0402--100nF--16V" C_0402HD 11.4,-9 r270 bottom value=100nF (schematic designator C2)
C17 "C_0402--100nF--16V" C_0402HD 9.3,-2 r90 bottom value=100nF (schematic designator C4)
C18 "C_0402--10nF--50V" C_0402HD 11.325,-3.1 r180 bottom value=10nF (schematic designator C1)
C19 "C_0402--100nF--16V" C_0402HD 5.8,-2 r90 bottom value=100nF (schematic designator C2)
C20 "C_0402--10nF--50V" C_0402HD 4.45,6.5 r90 bottom value=10nF (schematic designator C2)
C21 "C_0402--100nF--16V" C_0402HD 2.1,-2.4 r90 bottom value=100nF (schematic designator C1)
C22 "C_0402--100nF--16V" C_0402HD 1.7,2.5 r180 bottom value=100nF (schematic designator C1)
C23 "C_0402--100nF--16V" C_0402HD 1.7,3.4 r0 bottom value=100nF (schematic designator C10)
C24 "C_0402--1uF--6.3V" C_0402HD 1.1,-2.4 r90 bottom value=1uF (schematic designator C5)
C25 "C_0402--100nF--16V" C_0402HD 0.2,-2.4 r90 bottom value=100nF (schematic designator C4)
C26 "C_0402--100nF--16V" C_0402HD -0.3,1.2 r180 bottom value=100nF (schematic designator C3)
C27 "C_0402--1nF--50V/NP0" C_0402HD -0.3,-6.4 r90 bottom value=1nF (schematic designator C6)
C28 "C_0402--1nF--50V/NP0" C_0402HD -1.175,-6.4 r90 bottom value=1nF (schematic designator C5)
C29 "C_0402--10nF--50V" C_0402HD -1.65,-4 r0 bottom value=10nF (schematic designator C1)
C30 "C_0402--1nF--50V/NP0" C_0402HD -2.075,-6.4 r90 bottom value=1nF (schematic designator C4)
C31 "C_0402--10nF--50V" C_0402HD -2.2,1.2 r0 bottom value=10nF (schematic designator C3)
C32 "C_0402--100nF--16V" C_0402HD -3.425,-6.9 r0 bottom value=100nF (schematic designator C15)
C33 "C_0402--10nF--50V" C_0402HD -3.025,-4.525 r270 bottom value=10nF (schematic designator C2)
C34 "C_0402--10nF--50V" C_0402HD -3.9,-0.85 r90 bottom value=10nF (schematic designator C6)
C35 "C_0402--100nF--16V" C_0402HD -6.925,-3.075 r270 top value=100nF (schematic designator C1)
C36 "C_0402--100pF--50V" C_0402HD -4.975,7 r0 bottom value=100pF (schematic designator C14)
C37 "C_0402--100pF--50V" C_0402HD -8.375,13.7 r180 bottom value=100pF (schematic designator C12)
C38 "C_0805--1uF--100V/X7S" C_0805_1.45mm -8.8,-7.675 r90 bottom value=1uF (schematic designator C5)
C39 "C_0402--100pF--50V" C_0402HD -10.275,13.7 r180 bottom value=100pF (schematic designator C13)
C40 "C_0402--680pF--50V/C0G" C_0402HD -19.8,-5.486 r180 bottom value=680pF (schematic designator C3)
C41 "C_0402--1uF--10V" C_0402HD -19.8,-7.2 r0 bottom value=1uF (schematic designator C1)
C42 "C_0805--1uF--100V/X7S" C_0805 -11.125,2.575 r0 bottom value=1uF (schematic designator C7)
C43 "C_0402--100pF--50V" C_0402HD -11.7,13.2 r270 bottom value=100pF (schematic designator C11)
C44 "C_0402--1uF--10V" C_0402HD -12.025,-8.1 r0 bottom value=1uF (schematic designator C4)
C45 "C_0402--10nF--50V" C_0402HD -19.8,-4.629 r0 bottom value=10nF (schematic designator C2)
C46 "C_0603--100nF--100V/X7S" C_0603#1 -8.75,-4.75 r90 bottom value=100nF (schematic designator C6)
C47 "C_0402--18pF--50V" C_0402HD -19.8,-1.2 r0 bottom value=18pF (schematic designator C8)
C48 "C_0402--100nF--16V" C_0402HD -13.7,-0.5 r0 bottom value=100nF (schematic designator C13)
C49 "C_0402--1uF--10V" C_0402HD -10.6,-4 r270 bottom value=1uF (schematic designator C15)
C50 "C_0402--1uF--10V" C_0402HD -10.225,-5.35 r180 bottom value=1uF (schematic designator C14)
C51 "C_0402--47nF--25V" C_0402HD -19.8,-2.057 r0 bottom value=47nF (schematic designator C11)
C52 "C_0805--1uF--100V/X7S" C_0805_1.45mm -9.7,-2.1 r180 bottom value=1uF (schematic designator C17)
C53 "C_0603--10uF--10V/X7T" C_0603#1 -6.525,-2.125 r0 bottom value=10uF (schematic designator C17)
C54 "C_0805--1uF--100V/X7S" C_0805_1.45mm -9.85,-0.35 r0 bottom value=1uF (schematic designator C16)
C56 "C_0402--100nF--16V" C_0402HD -6.7,-3.225 r0 bottom value=100nF (schematic designator C9)
C57 "C_0402--100nF--16V" C_0402HD -6.625,-6.925 r0 bottom value=100nF (schematic designator C19)
C58 "C_0805--1uF--100V/X7S" C_0805_1.45mm -10.95,-12.825 r270 bottom value=1uF (schematic designator C18)
C59 "C_0805--1uF--100V/X7S" C_0805_1.45mm -9.175,-12.825 r270 bottom value=1uF (schematic designator C19)
C60 "C_0805--1uF--100V/X7S" C_0805_1.45mm -9.85,-10.275 r0 bottom value=1uF (schematic designator C20)
D1 "SMAT70A" SMA/DO-214AC -11.4,3.1 r90 top value="TVS 70V"
D2 "GMF05C-HSF-GS08" LLP75-6L -2.425,-6 r0 top value="TVS 5x5V" (schematic designator D12)
D3 "SP3304NUTG" 10-UFDFN -1.9,4.5 r270 top locked value="TVS 4x3.3V" (schematic designator D21)
D4 "LED_0402_GREEN" LED_0402 -1.9,13.375 r90 top value=- (schematic designator D15)
D5 "LED_0603_GREEN_RED" LED_0603_DUAL -0.7,13.225 r90 top value=- (schematic designator D8)
D6 "GMF05C-HSF-GS08" LLP75-6L -0.075,-6 r0 top value="TVS 5x5V" (schematic designator D13)
D7 "LED_0603_GREEN_RED" LED_0603_DUAL 0.7,13.225 r90 top value=- (schematic designator D11)
D8 "SP3304NUTG" 10-UFDFN 2.1,4.5 r270 top locked value="TVS 4x3.3V" (schematic designator D20)
D9 "LED_0402_GREEN" LED_0402 1.9,13.375 r90 top value=- (schematic designator D14)
D10 "GMF05C-HSF-GS08" LLP75-6L 2.312,-6 r0 top value="TVS 5x5V" (schematic designator D7)
D11 "GMF05C-HSF-GS08" LLP75-6L 4.669,-6 r0 top value="TVS 5x5V" (schematic designator D3)
D12 "GMF05C-HSF-GS08" LLP75-6L 7.025,-6 r0 top value="TVS 5x5V" (schematic designator D4)
D13 "SPHV24-01ETG-C" SOD-882 7.7,3.3 r270 top value="TVS 24V" (schematic designator D9)
D14 "SPHV24-01ETG-C" SOD-882 7.7,4.7 r90 top value="TVS 24V" (schematic designator D5)
D15 "SPHV36-01" SOD-882 13.5,6.825 r90 bottom value="TVS 36V" (schematic designator D3)
D16 "NZ9F6V2T5G" SOD923 -12.3,8.275 r180 bottom value=- (schematic designator D10)
D17 "NZ9F6V2T5G" SOD923 -7.53,-1.12 r180 bottom value=- (schematic designator D16)
D18 "V2PM12HM3/H" MICROSMP#1 -7,1.175 r0 top value=-
D19 "V2PM12HM3/H" MICROSMP#2 -10.4,-7.5 r270 bottom value=- (schematic designator D1)
D20 "NHP220SFT3G" SOD123FL -7.57,1.43 r90 bottom value=- (schematic designator D6)
D21 "V2PM12HM3/H" MICROSMP#3 -7.625,5.425 r270 bottom value=- (schematic designator D2)
D22 "SPHV36-01" SOD-882 14.318,5.55 r0 bottom value="TVS 36V" (schematic designator D4)
D23 "BAS16P2T5G" SOD923 8.35,0.075 r270 bottom value=- (schematic designator D5)
D24 "BAS16P2T5G" SOD923 10.55,6.125 r90 bottom value=- (schematic designator D6)
D25 "BAS16P2T5G" SOD923 11.35,-12.54 r90 bottom value=- (schematic designator D17)
D26 "ESD9X5.0ST5G" SOD923 -1.6,-10.925 r0 top value=- (schematic designator D19)
FD1 "FIDUCIAL_PCB_1mm" FIDUCIAL_PCB#1 -26,0 r270 top locked value=-
FD2 "FIDUCIAL_PCB_1mm" FIDUCIAL_PCB#1 21.5,15.5 r270 top value=-
FD3 "FIDUCIAL_PCB_1mm" FIDUCIAL_PCB#1 21.5,-15.5 r270 top locked value=-
FD4 "FIDUCIAL_PCB_1mm" FIDUCIAL_PCB#2 -26,0 r270 bottom value=-
FD5 "FIDUCIAL_PCB_1mm" FIDUCIAL_PCB#2 21.5,15.5 r90 bottom value=-
FD6 "FIDUCIAL_PCB_1mm" FIDUCIAL_PCB#2 21.5,-15.5 r90 bottom value=-
FD7 "FIDUCIAL_PANEL" FIDUCIAL_PANEL -25.5,-13 r0 top value=-
FD8 "FIDUCIAL_PANEL" FIDUCIAL_PANEL -19.5,-19 r0 top value=-
FD9 "FIDUCIAL_PANEL" FIDUCIAL_PANEL 123.5,136 r270 top value=-
FD10 "FIDUCIAL_PANEL" FIDUCIAL_PANEL 129.5,130 r0 top value=-
H1 "SolderPad_2.6mm_Edge" SOLDERPAD_2.6MM_EDGE -19,1.62 r90 top locked net-tie value=- (schematic designator H5)
H2 "SolderPad_2.6mm_Edge" SOLDERPAD_2.6MM_EDGE -19,6.7 r90 top locked net-tie value=- (schematic designator H3)
H3 "SolderPad_2.6mm_Edge" SOLDERPAD_2.6MM_EDGE 19,-6.7 r270 top locked net-tie value=- (schematic designator H6)
H4 "SolderPad_2.6mm_Edge" SOLDERPAD_2.6MM_EDGE 19,-1.62 r270 top locked net-tie value=-
H5 "SolderPad_2.6mm_Edge" SOLDERPAD_2.6MM_EDGE 19,3.46 r270 top locked net-tie value=- (schematic designator H2)
H6 "SolderPad_2.6mm_Edge" SOLDERPAD_2.6MM_EDGE 19,8.54 r270 top locked net-tie value=- (schematic designator H1)
L1 "L_SRN6045--47uH" L_SRN6045 -5.875,-10.975 r90 top value=47uH (schematic designator L2)
L2 "SRF2012A-900YA" ACM2012E -5.71,8.82 r0 top value=90Z
L3 "SRF2012A-900YA" ACM2012E -5.7,11.28 r0 top locked value=90Z (schematic designator L1)
L4 "L_0402" L_0402HD -5.15,-5.2 r270 top value=1000Z (schematic designator L3)
L5 "SRF2012A-900YA" ACM2012E 5.7,9.01 r180 top value=90Z (schematic designator L1)
L6 "SRF2012A-900YA" ACM2012E 5.7,11.3 r180 top locked value=90Z (schematic designator L2)
L7 "L_0402" L_0402HD 0.2,-0.5 r90 bottom value=1000Z (schematic designator L1)
L8 "L_0402" L_0402HD -3.425,-5.9 r0 bottom value=1000Z (schematic designator L4)
L9 "L_0603" L_0603#1 -9.075,1.925 r270 bottom value=470Z/1A (schematic designator L1)
L10 "L_0603" L_0603#2 -11.95,0.325 r270 bottom value=470Z/1A (schematic designator L2)
L11 "FB_0603" L_0603#2 -6,-5.1 r90 bottom value=220Z/2.5A (schematic designator L5)
L12 "FB_0603" L_0603#2 -7.3,-5.1 r90 bottom value=220Z/2.5A (schematic designator L6)
LABEL1 "LabelPCB" LABEL_PCB_6X6_AssemblyDrawings 12.25,-18.1 r180 bottom net-tie value=-
LAYERS1 "Mark8layersSmall" Mark8LayersHDI -19.125,-9.248 r0 top net-tie value=-
M1 "SPACER_SMD_ROUND_M2.5x3mm_NO_THREAD" WURTH_9774030951R_SMALL 15.25,-11 r0 bottom locked value=- (schematic designator M4)
M2 "SPACER_SMD_ROUND_M2.5x3mm_NO_THREAD" WURTH_9774030951R_SMALL 15.25,11 r0 bottom locked value=-
M3 "SPACER_SMD_ROUND_M2.5x3mm_NO_THREAD" WURTH_9774030951R_SMALL -15.25,-11 r0 bottom locked value=-
M4 "SPACER_SMD_ROUND_M2.5x3mm_NO_THREAD" WURTH_9774030951R_SMALL -15.25,11 r0 bottom locked value=- (schematic designator M1)
NT1 "NT_TOP_1.2x0.2" NETTIE-TOP -8.05,-6.9 r0 top net-tie value=-
ORIGIN1 "ORIGIN" ORIGIN 0,0 r270 top locked value=-
P1 "PAD_1.65mmTH" PAD_1.65MMTH -14.1,2 r180 top locked value=-
P2 "PAD_1.65mmTH" PAD_1.65MMTH -14.1,6 r180 top locked value=-
P3 "MOLEX_5019400507" MOLEX_5019400507 -9.5,10.3 r270 top locked value=-
P4 "MOLEX_501190-3017" MOLEX_501190-3017 3.5,-1.5 r180 top locked value=-
P5 "MOLEX_501190-2027" MOLEX_501190-2027 6.1,-10.5 r0 top locked value=-
P6 "MOLEX_5019400507" MOLEX_5019400507 9.5,10.3 r90 top locked value=-
P7 "PAD_1.65mmTH" PAD_1.65MMTH 14.1,-6 r180 top locked value=-
P8 "PAD_1.65mmTH" PAD_1.65MMTH 14.1,-2 r180 top locked value=-
P9 "PAD_1.65mmTH" PAD_1.65MMTH 14.1,2 r180 top locked value=-
P10 "HIROSE_DF12(3.0)-80DS-0.5V(86)" HIROSE_DF12(3.0)-80DS-0.5V(86)_ROTATED -0.5,10.2 r0 bottom value=-
P11 "HIROSE_DF12(3.0)-60DS-0.5V(86)" HIROSE_DF12(3.0)-60DS-0.5V(86) 1.45,-10.2 r0 bottom locked value=-
Q1 "SSM6K361NU" 6-UDFNB(2X2) -6.475,-0.9 r90 top value=-
Q2 "AON7254" 8-POWERWDFN(3.3X3.3) -11.2,-8.175 r270 top value=150V
Q3 "AON7254" 8-POWERWDFN(3.3X3.3) -10.735,-12.425 r270 top value=150V (schematic designator Q1)
Q4 "BSS139H6327XTSA1" SOT23-3N 8.65,3.75 r0 bottom value=- (schematic designator Q1)
Q5 "BSS139H6327XTSA1" SOT23-3N 11.05,3.725 r0 bottom locked value=- (schematic designator Q2)
Q6 "SI7113" POWERPAK_1212-8 -10.525,5.475 r0 bottom value=- (schematic designator Q2)
Q7 "MMBT5551M3T5G" SOT-723#1 -4.825,3.575 r90 bottom value=- (schematic designator Q3)
Q8 "MMBT5551M3T5G" SOT-723#2 -5.87,1.88 r270 bottom value=- (schematic designator Q5)
Q9 "MMBT5551M3T5G" SOT-723#2 -4.225,1.85 r90 bottom value=- (schematic designator Q4)
R1 "R_0402--20K--1%" R_0402HD#1 -5.58,-0.64 r90 bottom value=20K (schematic designator R22)
R2 "R_0402--100K--1%" R_0402HD#1 -5.375,5.325 r90 bottom value=100K (schematic designator R23)
R3 "R_0402--100K--1%" R_0402HD#1 -4.06,0.58 r0 bottom value=100K (schematic designator R24)
R4 "VC120648D101DP" R_1206_1MM -9,3.975 r270 top value=48VDC (schematic designator R1)
R5 "R_0402--1k65--0.1%" R_0402HD#1 -4.125,-5.95 r90 top value=1k65 (schematic designator R19)
R6 "R_0402--10K--1%" R_0402HD#1 -2.225,-7.45 r0 top value=10K (schematic designator R20)
R7 "AVR-M1005C180MTAAB" R_0402HD#1 -4.725,-2.7 r90 bottom value=-
R8 "AVR-M1005C180MTAAB" R_0402HD#1 -4.775,-6.4 r90 bottom value=- (schematic designator R1714)
R9 "R_0402--75R--1%" R_0402HD#1 -6.225,10.125 r180 top value=75R (schematic designator R2)
R10 "R_0402--75R--1%" R_0402HD#1 -4.4,10.1 r180 top value=75R (schematic designator R1)
R11 "R_0402--220R--1%,200mW" R_0402HD#1 9,-5.6 r180 top value=220R
R12 "R_0402--220R--1%,200mW" R_0402HD#1 -0.85,-7.95 r90 top value=220R (schematic designator R7)
R13 "R_0402--220R--1%,200mW" R_0402HD#1 -1.58,-10.12 r180 top value=220R (schematic designator R3)
R14 "R_0402--75R--1%" R_0402HD#2 6.375,10.15 r180 top value=75R (schematic designator R1)
R15 "R_0402--75R--1%" R_0402HD#3 4.625,10.15 r180 top value=75R (schematic designator R2)
R16 "R_0402--220R--1%,200mW" R_0402HD#1 9.025,-6.425 r0 top value=220R (schematic designator R15)
R17 "R_1206--1k--1%,0.75W" R_1206_HD 14.325,4.95 r0 top value=1k (schematic designator R4)
R18 "R_1206--1k--1%,0.75W" R_1206_HD 14.325,7 r0 top value=1k (schematic designator R1)
R19 "R_0402--220R--1%,200mW" R_0402HD#1 12.05,8.1 r90 bottom locked value=220R (schematic designator R7)
R20 "R_0402--20K--1%" R_0402HD#1 11.325,-1.325 r180 bottom value=20K (schematic designator R3)
R21 "R_0402--20K--1%" R_0402HD#1 11.325,-2.213 r180 bottom value=20K (schematic designator R2)
R22 "R_0402--3k74--1%" R_0402HD#1 7.9,13.7 r180 bottom value=3k74 (schematic designator R2)
R23 "R_0402--20K--1%" R_0402HD#1 6.2,6.5 r90 bottom value=20K (schematic designator R6)
R24 "R_0402--20K--1%" R_0402HD#1 5.325,6.5 r90 bottom value=20K (schematic designator R5)
R25 "R_0402--1K--1%" R_0402HD#1 6,13.7 r0 bottom value=1K (schematic designator R8)
R26 "R_0402--1K--1%" R_0402HD#1 3.575,6.5 r90 bottom value=1K (schematic designator R17)
R27 "R_0402--1K--1%" R_0402HD#1 4.1,13.7 r180 bottom value=1K (schematic designator R10)
R28 "R_0402--1K--1%" R_0402HD#1 2.7,6.5 r90 bottom value=1K (schematic designator R13)
R29 "R_0402--3k74--1%" R_0402HD#1 -6.5,13.7 r180 bottom value=3k74 (schematic designator R3)
R30 "R_0402--10K--0.1%" R_0402HD#1 -0.3,-4.5 r90 bottom value=10K (schematic designator R2)
R31 "R_0402--1K--1%" R_0402HD#1 -1.575,13.7 r180 bottom value=1K (schematic designator R9)
R32 "R_0402--1k65--0.1%" R_0402HD#1 -1.65,-4.9 r0 bottom value=1k65 (schematic designator R1)
R33 "R_0402--1k65--0.1%" R_0402HD#1 -2.7,2.125 r0 bottom value=1k65 (schematic designator R5)
R34 "R_0402--10K--0.1%" R_0402HD#1 -2.7,3.1 r180 bottom value=10K (schematic designator R7)
R35 "R_0402--10K--0.1%" R_0402HD#1 -4.8,-4.5 r270 bottom value=10K (schematic designator R3)
R36 "R_0402--1k65--0.1%" R_0402HD#1 -3.875,-2.7 r270 bottom value=1k65 (schematic designator R6)
R37 "R_0402--1k65--0.1%" R_0402HD#1 -3.925,-4.525 r270 bottom value=1k65 (schematic designator R4)
R38 "R_0402--10K--0.1%" R_0402HD#1 -4.75,-0.85 r270 bottom value=10K (schematic designator R8)
R39 "R_0402--220R--1%,200mW" R_0402HD#1 11.15,8.1 r90 bottom locked value=220R (schematic designator R8)
R40 "R_0603--25mohm--1%" R_0603 -8.568,-6.9 r180 top value=25mohm (schematic designator R7)
R41 "R_0402--100K--1%" R_0402HD#1 -6.5,-5.7 r180 top value=100K (schematic designator R4)
R42 "R_0402--220R--1%,200mW" R_0402HD#4 -5.9,-3.075 r90 top value=220R (schematic designator R5)
R43 "R_0402--13K7--1%" R_0402HD#1 -19.8,-6.343 r180 bottom value=13K7 (schematic designator R1)
R44 "R_0402--1K2--1%" R_0402HD#1 -19.8,-3.771 r180 bottom value=1K2 (schematic designator R5)
R45 "R_0402--3k74--1%" R_0402HD#1 -15.5,-0.5 r180 bottom value=3k74 (schematic designator R6)
R46 "R_0402--1K2--1%" R_0402HD#1 -19.8,-2.914 r0 bottom value=1K2 (schematic designator R3)
R47 "R_0402--10K--1%" R_0402HD#1 9.8,13.7 r180 bottom value=10K (schematic designator R12)
R48 "R_0402--3k74--1%" R_0402HD#1 -0.475,-13.35 r90 top value=3k74 (schematic designator R6)
R49 "R_0402--20K--1%" R_0402HD#1 -6.38,-0.64 r90 bottom value=20K (schematic designator R11)
R50 "R_0402--220R--1%,200mW" R_0402HD#1 10.125,1.65 r180 bottom value=220R (schematic designator R9)
R51 "R_0402--75R--1%" R_0402HD#1 8.225,1.65 r180 bottom value=75R (schematic designator R10)
R52 "R_0402--220R--1%,200mW" R_0402HD#1 12.625,5.525 r0 bottom value=220R (schematic designator R11)
R53 "R_0402--75R--1%" R_0402HD#1 11.925,6.4 r180 bottom value=75R (schematic designator R12)
R54 "R_0402--100K--1%" R_0402HD#1 -1.85,-9.29 r180 top value=100K (schematic designator R14)
R55 "R_0402--220R--1%,200mW" R_0402HD#1 14.925,6.55 r0 bottom value=220R (schematic designator R14)
R56 "R_0402--220R--1%,200mW" R_0402HD#1 13.375,4.6 r0 bottom value=220R (schematic designator R13)
R57 "R_0402--100K--1%" R_0402HD#1 -2.22,-8.4 r0 top value=100K (schematic designator R15)
R58 "R_0402--220k--1%" R_0402hd -12.1,7.5 r0 bottom value=220k (schematic designator R21)
R59 "R_0402--100K--1%" R_0402HD#1 -6.325,5.45 r90 bottom value=100K (schematic designator R16)
R60 "R_0402--100K--1%" R_0402HD#1 -6.125,3.65 r90 bottom value=100K (schematic designator R18)
R61 "R_0402--100K--1%" R_0402HD#1 -4.5,5.325 r90 bottom value=100K (schematic designator R25)
R62 "R_0402--100K--1%" R_0402HD#1 -5.89,0.66 r0 bottom value=100K (schematic designator R26)
RN1 "R_ARRAY_0804_8--2K--5%" R_ARR_CRA04S08 7.6,-2 r180 bottom value=2K (schematic designator RN2)
RN2 "R_ARRAY_0804_8--2K--5%" R_ARR_CRA04S08 5.8,-0.2 r180 bottom value=2K (schematic designator RN3)
RN3 "R_ARRAY_0804_8--2K--5%" R_ARR_CRA04S08 5.8,1.5 r0 bottom value=2K (schematic designator RN1)
RN4 "R_ARRAY_0804_8--1K--1%" R_ARR_CRA04S08 4,-2 r0 bottom value=1K (schematic designator RN1)
RN5 "R_ARRAY_0804_8--10k--1%" R_ARR_CRA04S08 1.3,-6.4 r180 bottom value=10k
RN6 "R_ARRAY_0804_8--1K--1%" R_ARR_CRA04S08 1.3,-4.4 r180 bottom value=1K
RN7 "R_ARRAY_0804_8--470R--5%" R_ARR_0804_8 -0.6,2.7 r180 bottom value=470R (schematic designator RN4)
RN8 "R_ARRAY_0804_8--10k--1%" R_ARR_CRA04S08 -2.85,4.55 r180 bottom value=10k (schematic designator RN2)
RN9 "R_ARRAY_0804_8--15k--5%" R_ARR_CRA04S08 -2.85,6.475 r0 bottom value=15k (schematic designator RN3)
T1 "ALT4532P-181-T05G" TDK_ALT4523#1 -5.9,5.1 r90 top locked value=- (schematic designator T2)
T2 "ALT4532P-181-T05G" TDK_ALT4523#2 -1.85,9.1 r90 top locked value=- (schematic designator T1)
T3 "ALT4532P-181-T05G" TDK_ALT4523#3 1.8,9.1 r90 top locked value=- (schematic designator T2)
T4 "ALT4532P-181-T05G" TDK_ALT4523#4 5.4,5.3 r90 top locked value=- (schematic designator T1)
U1 "FPF2495UCX" 9-UFBGA -1.85,-13.4 r0 top value=- (schematic designator U6)
U2 "MCP2562-E/MF" DFN-8(3x3) 10.035,3.82 r180 top locked value=- (schematic designator U1)
U3 "TLP3403(TP,F" 4-VSON 8.325,6.3 r180 bottom value=1A (schematic designator U2)
U4 "SN65HVD78DRBR" VSON-8_(DFN-8)_NOVIAS 10.9,-5.8 r90 bottom locked value=- (schematic designator U1)
U5 "TLP3403(TP,F" 4-VSON 10.45,0.075 r0 bottom value=1A (schematic designator U1)
U6 "SN65HVD78DRBR" VSON-8_(DFN-8)_NOVIAS 7.5,-5.1 r90 bottom value=- (schematic designator U3)
U7 "MAX3280EAUK+T" SOT23-5N 4.6,4 r0 bottom value=- (schematic designator U1)
U8 "SN65HVD78DRBR" VSON-8_(DFN-8)_NOVIAS 4.1,-5.1 r90 bottom value=- (schematic designator U5)
U9 "MAX3280EAUK+T" SOT23-5N 2.7,0.4 r0 bottom value=- (schematic designator U2)
U10 "74AHCT125BQ" DHVQFN14 0.3,5.6 r90 bottom value=- (schematic designator U2)
U11 "OPA2316IDRGT" 8-WFDFN -1.9,-1.375 r90 bottom value=- (schematic designator U1)
U12 "SN74LVC3G04YZPR" 8-DSBGA -3.875,13.55 r90 bottom value=- (schematic designator U3)
U13 "SN74LVC1G17DRYR" 6-SON(1.45x1) -6.525,-4.6 r90 top value=- (schematic designator U1)
U14 "LM5116MH" TSOP20_065P_EP -15,-4.4 r0 bottom locked value=- (schematic designator U1)
U15 "NX5P3001UKZ" WLCSP12 11.575,13.25 r0 bottom value=- (schematic designator U4)

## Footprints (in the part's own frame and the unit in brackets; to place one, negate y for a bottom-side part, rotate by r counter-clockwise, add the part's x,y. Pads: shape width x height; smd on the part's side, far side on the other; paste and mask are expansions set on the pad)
4-VSON [mm] "vson 4 SOLID STATE RELAY FOOTPRINT"
  rrect50% 1x0.55 smd mask+0.07: 1(-0.875,0.4) 2(-0.875,-0.4) 3(0.875,-0.4) 4(0.875,0.4)
  silkscreen extent -1.55,0.8 -1.45,0.9, body extent -1.25,-0.75 1.25,0.75, height 1.4
6-SON(1.45x1) [mm] "SON, 6-Leads, Body 1,45x1,00mm, Pitch 0,50mm, IPC Medium Density"
  rrect70% 0.45x0.3 smd paste-0.05 mask-0.05: 1(-0.275,0.5)
  rrect70% 0.4x0.3 smd paste-0.05 mask-0.05: 2(-0.3,0) 3(-0.3,-0.5) 4(0.3,-0.5) 5(0.3,0) 6(0.3,0.5)
  silkscreen extent -0.7,0.75 -0.6,0.85, body extent -0.54,-0.75 0.54,0.75, height 0.6
6-UDFNB(2X2) [mm] "UDFN, 6-Leads, Body 2,00x2,00mm, Pitch 0,65mm, MOSFET, IPC Medium Density"
  rrect50% 0.45x0.3 smd paste+0 mask+0.05: 1(-0.975,0.65) 2(-0.975,0) 3(-0.975,-0.65) 4(0.975,-0.65) 5(0.975,0) 6(0.975,0.65)
  rrect50% 0.75x0.3 smd paste-0.05 mask+0.05: 7(0,-0.65)
  rrect20% 1x0.95 smd paste-0.05 mask+0.05: 8(0,0.325)
  silkscreen extent -1.07,1.15 -0.83,1.4, body extent -1.05,-1.05 1.05,1.05, height 0.8
8-DSBGA [mm] "BGA, 8-Leads, Body 1.9x0.9x0.5mm Pitch 0,5mm"
  round 0.23 smd paste-1 mask+0.05: A1(-0.25,0.75) A2(0.25,0.75) B1(-0.25,0.25) B2(0.25,0.25) C1(-0.25,-0.25) C2(0.25,-0.25) D1(-0.25,-0.75) D2(0.25,-0.75)
  rrect50% 0.25x0.25 on Bottom Paste: ""(-0.25,-0.75) ""(-0.25,-0.25) ""(-0.25,0.25) ""(-0.25,0.75) ""(0.25,-0.75) ""(0.25,-0.25) ""(0.25,0.25) ""(0.25,0.75)
  body extent -0.47,-0.98 0.47,0.98, height 0.5
8-POWERWDFN(3.3X3.3) [mm] "8-WDFN 3.3 x 3.3 mm Exposed pad"
  rect 0.7x0.42 smd paste+0 mask+0.05: 1(-1.4,0.975) 2(-1.4,0.325) 3(-1.4,-0.325) 4(-1.4,-0.975)
  rect 0.45x0.42 smd paste+0 mask+0.05: 5(1.525,-0.975) 6(1.525,-0.325) 7(1.525,0.325) 8(1.525,0.975)
  rect 1.7x2.37 smd paste-3 mask+0.05: 9(0.45,0)
  silkscreen extent -2.1,1.4 -1.85,1.65, body extent -1.7,-1.65 1.7,1.65, height 1.05
8-WFDFN [mm] "8-WFDFN 3 x 3 mm Exposed pad"
  rrect10% 1.2x2 smd paste-3: 0(0,0)
  rrect50% 0.95x0.28 smd paste+0 mask+0.07: 1(-1.425,0.75) 2(-1.425,0.25) 3(-1.425,-0.25) 4(-1.425,-0.75) 5(1.425,-0.75) 6(1.425,-0.25) 7(1.425,0.25) 8(1.425,0.75)
  silkscreen extent -2.1,1.4 -1.85,1.65, body extent -1.53,-1.5 1.53,1.5, height 1.05
9-UFBGA [mm] "BGA, 9-Leads, Body 1,21x1,21mmx0,63mm, Pitch 0,40mm"
  round 0.2 smd mask+0.05: A1(-0.4,0.4) A2(0,0.4) A3(0.4,0.4) B1(-0.4,0) B2(0,0) B3(0.4,0) C1(-0.4,-0.4) C2(0,-0.4) C3(0.4,-0.4)
  silkscreen extent -0.76,0.66 -0.66,0.76, body extent -0.61,-0.61 0.61,0.61, height 0.63
10-UFDFN [mm] "PQFN, 10-Leads, Body 2,60x2,60mm, Pitch 0,50mm, Thermal Pad 1,41x2,30mm, IPC Medium Density"
  rrect50% 0.55x0.35 smd mask+0.01: 1(-1.1,1) 2(-1.1,0.5) 3(-1.1,0) 4(-1.1,-0.5) 5(-1.1,-1) 6(1.1,-1) 7(1.1,-0.5) 8(1.1,0) 9(1.1,0.5) 10(1.1,1)
  rrect20% 1.25x2.3 smd mask+0.01: EP(0,0)
  silkscreen extent -1.85,1.4 -1.6,1.65, body extent -1.35,-1.35 1.35,1.35, height 0.55
ACM2012E [mm] "Common Mode choke for LAN"
  rrect50% 0.75x0.4 smd: 1(-0.925,0.4) 2(-0.925,-0.4) 3(0.925,-0.4) 4(0.925,0.4)
  body extent -1.03,-0.6 1.03,0.6, height 1
BREAKAWAY_VIAS_2MM [mm]
  round 0 hole 0.5 unplated mask+0: 0(-0.75,-0.2) 0(0.75,-0.2)
  round 0 hole 0.4 unplated mask+0: 0(0,-0.25)
  Keep-Out Layer lines w0.2: -1.15,0 -1.15,-0.2 ccw(c-0.75,-0.2) -0.75,-0.6 0.75,-0.6 ccw(c0.75,-0.2) 1.15,-0.2 1.15,0
  body extent -0.01,-0.26 0.01,-0.24
BREAKAWAY_VIAS_3.4MM [mm]
  round 0 hole 0.5 unplated mask+0: 0(-1.45,-0.2) 0(1.45,-0.2)
  round 0 hole 0.4 unplated mask+0: 0(-0.7,-0.25) 0(0,-0.25) 0(0.7,-0.25)
  Keep-Out Layer lines w0.2: 1.85,0 1.85,-0.2 cw(c1.45,-0.2) 1.45,-0.6 -1.45,-0.6 cw(c-1.45,-0.2) -1.85,-0.2 -1.85,0
  body extent -0.01,-0.26 0.01,-0.24
C_0402HD [mm] "Chip Capacitor, Body 1.0x0.5mm, IPC High Density"
  rrect50% 0.6x0.6 smd: 1(-0.5,0) 2(0.5,0)
  body extent -0.53,-0.28 0.53,0.28, height 0.5
C_0603#1 [mm] "Chip Capacitor, Body 1.6x0.8mm, IPC Medium Density"
  rrect50% 0.9x1 smd: 1(-0.8,0) 2(0.8,0)
  silkscreen extent 0,-0.45 0,0.45, body extent -0.85,-0.45 0.85,0.45, height 0.8
C_0603#2 [mm] "Chip Capacitor, Body 1.6x0.8mm, IPC Medium Density"
  rrect50% 0.9x0.95 smd: 1(-0.8,0) 2(0.8,0)
  silkscreen extent 0,-0.45 0,0.45, body extent -0.85,-0.45 0.85,0.45, height 0.8
C_0805 [mm] "Chip Capacitor, Body 2.0x1.3mm, IPC Medium Density"
  rrect50% 1.1x1.5 smd: 1(-0.85,0) 2(0.85,0)
  silkscreen extent 0,-0.7 0,0.7, body extent -1.1,-0.7 1.1,0.7, height 1
C_0805_1.45mm [mm] "Chip Capacitor, Body 2.0x1.3mm, IPC Medium Density"
  rrect50% 1.1x1.5 smd: 1(-0.85,0) 2(0.85,0)
  silkscreen extent 0,-0.7 0,0.7, body extent -1.1,-0.7 1.1,0.7, height 1.45
C_1206 [mm] "Chip Capacitor, Body 3.2x1.6mm, IPC Medium Density"
  rrect50% 1.3x1.8 smd: 1(-1.45,0) 2(1.45,0)
  silkscreen extent -0.4,-0.8 0.4,0.8, body extent -1.6,-0.8 1.62,0.8, height 1
C_J-LEAD_2STACK_6.1X5.3MM [mm] "Dual Stacked Chip Capacitor, Body 6.1x5.3mm"
  rrect30% 1.8x5.7 smd: 1(-2.5,0) 2(2.5,0)
  silkscreen extent -1,-2.7 1,2.7, body extent -3.1,-2.7 3.1,2.7, height 6.7
DFN-8(3x3) [mm] "8-DFN 3 x 3 mm Exposed pad"
  rrect50% 0.5x0.35 smd paste+0 mask+0.06: 1(-1.4,0.975) 2(-1.4,0.325) 3(-1.4,-0.325) 4(-1.4,-0.975) 5(1.4,-0.975) 6(1.4,-0.325) 7(1.4,0.325) 8(1.4,0.975)
  rrect10% 1.5x2.38 smd paste-3: 9(0,0)
  silkscreen extent -2.1,1.4 -1.85,1.65, body extent -1.55,-1.5 1.55,1.5, height 1.05
DHVQFN14 [mm] "QFN, 14-Leads, Body 2,50x3,00mm, Pitch 0,50mm, Thermal Pad 1,00x1,50mm, IPC Medium Density"
  oval 0.28x0.8 smd mask+0.05: 1(-0.25,1.5) 7(-0.25,-1.5) 8(0.25,-1.5) 14(0.25,1.5)
  oval 0.8x0.28 smd mask+0.05: 2(-1.25,1) 3(-1.25,0.5) 4(-1.25,0) 5(-1.25,-0.5) 6(-1.25,-1) 9(1.25,-1) 10(1.25,-0.5) 11(1.25,0) 12(1.25,0.5) 13(1.25,1)
  rrect20% 1x1.5 smd paste-2 mask+0.05: EP(0,0)
  silkscreen extent -0.82,2.08 -0.58,2.33, body extent -1.32,-1.57 1.32,1.57, height 1.01
FIDUCIAL_PANEL [mm] "Double layer fiducial point for the panel"
  round 1 on Mech16 paste+0 mask+0: 1(0,0)
FIDUCIAL_PCB#1 [mm] "Single layer fiducial point for the PCB. 1 mm copper diameter 3 mm total diameter."
  round 0.5 on Mech10 paste+0 mask+0: 1(0,0)
  Top Layer region: 0,0.5 0.191,0.462 0.354,0.354 0.462,0.191 0.5,0 0.5,0 0.462,-0.191 0.354,-0.354 0.191,-0.462 0,-0.5 0,-0.5 -0.191,-0.462 -0.354,-0.354 -0.462,-0.191 -0.5,0 -0.5,0 -0.462,0.191 -0.354,0.354 -0.191,0.462 0,0.5
  Top Layer pour cut-out: 0,1.5 0.574,1.386 1.061,1.061 1.386,0.574 1.5,0 1.5,0 1.386,-0.574 1.061,-1.061 0.574,-1.386 0,-1.5 0,-1.5 -0.574,-1.386 -1.061,-1.061 -1.386,-0.574 -1.5,0 -1.5,0 -1.386,0.574 -1.061,1.061 -0.574,1.386 0,1.5
  body extent 0,0 0,0
FIDUCIAL_PCB#2 [mm] "Single layer fiducial point for the PCB. 1 mm copper diameter 3 mm total diameter."
  round 0.5 on Mech11 paste+0 mask+0: 1(0,0)
  Top Layer pour cut-out: 0,1.5 0.574,1.386 1.061,1.061 1.386,0.574 1.5,0 1.5,0 1.386,-0.574 1.061,-1.061 0.574,-1.386 0,-1.5 0,-1.5 -0.574,-1.386 -1.061,-1.061 -1.386,-0.574 -1.5,0 -1.5,0 -1.386,0.574 -1.061,1.061 -0.574,1.386 0,1.5
  Top Layer region: 0,0.5 0.191,0.462 0.354,0.354 0.462,0.191 0.5,0 0.5,0 0.462,-0.191 0.354,-0.354 0.191,-0.462 0,-0.5 0,-0.5 -0.191,-0.462 -0.354,-0.354 -0.462,-0.191 -0.5,0 -0.5,0 -0.462,0.191 -0.354,0.354 -0.191,0.462 0,0.5
  body extent 0,0 0,0
HIROSE_DF12(3.0)-60DS-0.5V(86) [mm] "CONN HEADER 60POS 5MM SMD 0.5MM"
  rrect50% 0.3x1.6 smd: 1(-7.25,1.8) 2(-7.25,-1.8) 3(-6.75,1.8) 4(-6.75,-1.8) 5(-6.25,1.8) 6(-6.25,-1.8) 7(-5.75,1.8) 8(-5.75,-1.8) 9(-5.25,1.8) 10(-5.25,-1.8) 11(-4.75,1.8) 12(-4.75,-1.8) 13(-4.25,1.8) 14(-4.25,-1.8) 15(-3.75,1.8) 16(-3.75,-1.8) 17(-3.25,1.8) 18(-3.25,-1.8) 19(-2.75,1.8) 20(-2.75,-1.8) 21(-2.25,1.8) 22(-2.25,-1.8) 23(-1.75,1.8) 24(-1.75,-1.8) 25(-1.25,1.8) 26(-1.25,-1.8) 27(-0.75,1.8) 28(-0.75,-1.8) 29(-0.25,1.8) 30(-0.25,-1.8) 31(0.25,1.8) 32(0.25,-1.8) 33(0.75,1.8) 34(0.75,-1.8) 35(1.25,1.8) 36(1.25,-1.8) 37(1.75,1.8) 38(1.75,-1.8) 39(2.25,1.8) 40(2.25,-1.8) 41(2.75,1.8) 42(2.75,-1.8) 43(3.25,1.8) 44(3.25,-1.8) 45(3.75,1.8) 46(3.75,-1.8) 47(4.25,1.8) 48(4.25,-1.8) 49(4.75,1.8) 50(4.75,-1.8) 51(5.25,1.8) 52(5.25,-1.8) 53(5.75,1.8) 54(5.75,-1.8) 55(6.25,1.8) 56(6.25,-1.8) 57(6.75,1.8) 58(6.75,-1.8) 59(7.25,1.8) 60(7.25,-1.8)
  round 0 hole 0.6 unplated: H1(-8.3,1.5) H2(8.3,1.5)
  rrect20% 0.8x2 smd: S1(-8.9,0) S2(8.9,0)
  Keep-Out Layer circle w0.24: c8.3,1.5 r0.43
  Keep-Out Layer circle w0.24: c-8.3,1.5 r0.43
  body extent -9.05,-2.3 9.05,2.3, height 2.2
HIROSE_DF12(3.0)-80DS-0.5V(86)_ROTATED [mm] "CONN HEADER 80POS 3MM SMD 0.5MM"
  rrect50% 0.3x1.6 smd paste+0 mask+0.05: 1(-9.75,1.8) 2(-9.75,-1.8) 3(-9.25,1.8) 4(-9.25,-1.8) 5(-8.75,1.8) 6(-8.75,-1.8) 7(-8.25,1.8) 8(-8.25,-1.8) 9(-7.75,1.8) 10(-7.75,-1.8) 11(-7.25,1.8) 12(-7.25,-1.8) 13(-6.75,1.8) 14(-6.75,-1.8) 15(-6.25,1.8) 16(-6.25,-1.8) 17(-5.75,1.8) 18(-5.75,-1.8) 19(-5.25,1.8) 20(-5.25,-1.8) 21(-4.75,1.8) 22(-4.75,-1.8) 23(-4.25,1.8) 24(-4.25,-1.8) 25(-3.75,1.8) 26(-3.75,-1.8) 27(-3.25,1.8) 28(-3.25,-1.8) 29(-2.75,1.8) 30(-2.75,-1.8) 31(-2.25,1.8) 32(-2.25,-1.8) 33(-1.75,1.8) 34(-1.75,-1.8) 35(-1.25,1.8) 36(-1.25,-1.8) 37(-0.75,1.8) 38(-0.75,-1.8) 39(-0.25,1.8) 40(-0.25,-1.8) 41(0.25,1.8) 42(0.25,-1.8) 43(0.75,1.8) 44(0.75,-1.8) 45(1.25,1.8) 46(1.25,-1.8) 47(1.75,1.8) 48(1.75,-1.8) 49(2.25,1.8) 50(2.25,-1.8) 51(2.75,1.8) 52(2.75,-1.8) 53(3.25,1.8) 54(3.25,-1.8) 55(3.75,1.8) 56(3.75,-1.8) 57(4.25,1.8) 58(4.25,-1.8) 59(4.75,1.8) 60(4.75,-1.8) 61(5.25,1.8) 62(5.25,-1.8) 63(5.75,1.8) 64(5.75,-1.8) 65(6.25,1.8) 66(6.25,-1.8) 67(6.75,1.8) 68(6.75,-1.8) 69(7.25,1.8) 70(7.25,-1.8) 71(7.75,1.8) 72(7.75,-1.8) 73(8.25,1.8) 74(8.25,-1.8) 75(8.75,1.8) 76(8.75,-1.8) 77(9.25,1.8) 78(9.25,-1.8) 79(9.75,1.8) 80(9.75,-1.8)
  round 0 hole 0.6 unplated: H1(10.8,-1.5) H2(-10.8,-1.5)
  rrect20% 0.8x2 smd: S1(-11.4,0) S2(11.4,0)
  Keep-Out Layer circle w0.23: c10.8,-1.5 r0.42
  Keep-Out Layer circle w0.23: c-10.8,-1.5 r0.42
  body extent -11.55,-2.3 11.55,2.3, height 2.2
L_0402HD [mm] "Ferrite bead Body 1.0x0.5mm, IPC High Density"
  rrect50% 0.6x0.6 smd: 1(-0.5,0) 2(0.5,0)
  body extent -0.53,-0.28 0.53,0.28, height 0.5
L_0603#1 [mm] "Coil 0603"
  rrect50% 0.85x0.85 smd: 1(-0.85,0)
  rrect50% 0.9x1 smd: 2(0.85,0)
  silkscreen extent -0.1,-0.1 0.1,0.1, body extent -1,-0.45 1,0.45, height 0.8
L_0603#2 [mm] "Coil 0603"
  rrect50% 0.9x1 smd: 1(-0.85,0) 2(0.85,0)
  silkscreen extent -0.1,-0.1 0.1,0.1, body extent -1,-0.45 1,0.45, height 0.8
L_SRN6045 [mm] "Bourns SRN6045 inductors"
  rrect50% 1.5x4.8 smd: 1(-2.1,0)
  rrect50% 2.3x4.8 smd: 2(2.1,0)
  silkscreen extent -0.2,-0.2 0.2,0.2, body extent -3.15,-3 3.15,3, height 4.47
LABEL_PCB_6X6_AssemblyDrawings [mm]
LED_0402 [mm] "SMD diode 0402"
  rrect50% 0.7x0.5 smd: 1(-0.475,0) 2(0.475,0)
  silkscreen extent 1.02,-0.3 1.02,0.3, body extent -0.5,-0.25 0.5,0.25, height 0.49
LED_0603_DUAL [mm] "LED 0603 1.6x0.8mm Bicolor"
  rrect30% 0.7x0.4 smd: 1(-0.65,0.35) 2(-0.65,-0.35) 3(0.65,0.35) 4(0.65,-0.35)
  silkscreen extent 1.25,-0.4 1.25,0.45, body extent -0.82,-0.35 0.82,0.38, height 0.68
LLP75-6L [mm] "DFN, 6-Leads, Body 2,01x1,81mm, Pitch 0,50mm, Thermal Pad 1,00x1,40mm, IPC Medium Density"
  rrect30% 0.5x0.25 smd mask+0.05: 1(-0.75,0.5) 3(-0.75,-0.5) 4(0.75,-0.5) 5(0.75,0) 6(0.75,0.5)
  rrect30% 0.85x0.25 smd mask+0.05: 2(-0.55,0)
  rrect20% 0.5x1 smd mask+0.07: 2(0,0)
  silkscreen extent -1.1,0.8 -1,0.9, body extent -0.82,-0.82 0.82,0.82, height 0.6
Mark8LayersHDI [mm]
  body extent 0.19,0.39 0.21,0.41
MICROSMP#1 [mm] "MicroSMP Small Signal Diodes"
  rrect40% 0.75x0.8 smd: 1(-1.25,0)
  rrect10% 2x1.1 smd: 2(0.75,0)
  silkscreen extent 2,-0.5 2,0.5, body extent -1.35,-0.7 1.35,0.7, height 0.73
MICROSMP#2 [mm] "MicroSMP Small Signal Diodes"
  rrect10% 0.8x0.8 smd: 1(-1.25,0)
  rrect20% 2x1.1 smd: 2(0.75,0)
  silkscreen extent 2,-0.5 2,0.5, body extent -1.35,-0.7 1.35,0.7, height 0.73
MICROSMP#3 [mm] "MicroSMP Small Signal Diodes"
  rrect10% 0.8x0.8 smd: 1(-1.25,0)
  rrect10% 2x1 smd: 2(0.75,0)
  silkscreen extent 2,-0.5 2,0.5, body extent -1.35,-0.7 1.35,0.7, height 0.73
MOLEX_501190-2027 [mm]
  rrect50% 0.6x1.6 smd: 1(-4.5,-2.8) 3(-3.5,-2.8) 4(-3.5,2.8) 5(-2.5,-2.8) 6(-2.5,2.8) 7(-1.5,-2.8) 8(-1.5,2.8) 9(-0.5,-2.8) 10(-0.5,2.8) 11(0.5,-2.8) 12(0.5,2.8) 13(1.5,-2.8) 14(1.5,2.8) 15(2.5,-2.8) 16(2.5,2.8) 17(3.5,-2.8) 18(3.5,2.8) 19(4.5,-2.8) 20(4.5,2.8)
  rrect70% 0.6x1.6 smd: 2(-4.5,2.8)
  rrect50% 1.2x2 smd: S1(-6,0.4)
  rrect50% 1.15x2 smd mask+0: S2(6,0.4)
  silkscreen extent -6.06,-3.06 -5.94,-2.94, body extent -6.15,-4.07 6.15,3.2, height 5.39
MOLEX_501190-3017 [mm] "Connector male header shrouded SMD, 30 ways, 2 row, 1 mm pitch"
  rrect50% 0.6x1.6 smd: 1(-7,-2.8) 2(-7,2.8) 3(-6,-2.8) 4(-6,2.8) 5(-5,-2.8) 6(-5,2.8) 7(-4,-2.8) 8(-4,2.8) 9(-3,-2.8) 10(-3,2.8) 11(-2,-2.8) 12(-2,2.8) 13(-1,-2.8) 14(-1,2.8) 15(0,-2.8) 16(0,2.8) 17(1,-2.8) 18(1,2.8) 19(2,-2.8) 20(2,2.8) 21(3,-2.8) 22(3,2.8) 23(4,-2.8) 24(4,2.8) 26(5,2.8) 28(6,2.8)
  rrect50% 0.6x1.45 smd: 25(5,-2.8)
  rrect50% 0.5x1.45 smd: 27(6,-2.8)
  rrect50% 0.5x1.6 smd: 29(7,-2.8)
  rrect50% 0.6x1.5 smd: 30(7,2.8)
  rrect50% 0.85x1.8 smd: S1(-8.325,0.4) S2(8.325,0.4)
  silkscreen extent -8.7,-3.56 8.7,2.82, body extent -8.65,-4.12 8.65,3.15, height 5.57
MOLEX_5019400507 [mm]
  rrect50% 0.6x1.6 smd: 1(2,1.2) 2(1,1.2) 3(0,1.2) 4(-1,1.2) 5(-2,1.2)
  rrect50% 1.2x1.8 smd: S1(3.3,-1.3) S2(-3.3,-1.3)
  body extent -3.62,-3.35 3.62,1.7, height 5.42
NETTIE-TOP [mm] "net tie for joining two different nets"
  rect 0.6x0.2 smd paste-5 mask-5: 1(-0.2,0) 2(0.2,0)
  body extent 0,0 0,0
ORIGIN [mm] "Origin of coordinate axes for pick and place"
  round 0.5 on Mech10 paste+0 mask+0: 1(0,0) 1(0,0)
  round 0.5 on Mech16 paste+0 mask+0: 1(0,0) 1(0,0)
  round 0.5 on Mech11 paste+0 mask+0: 1(0,0) 1(0,0)
  body extent 0,0 0,0
PAD_1.65MMTH [mm] "1.65mm TH pad for direct cable connection"
  oval 2.7x2.6 hole 1.7: 1(0,0)
POWERPAK_1212-8 [mm] "PowerPAK_1212-8 3.3 x 3.3 mm Exposed pad"
  rrect50% 0.99x0.405 smd paste+0 mask+0.05: 1(-1.4,0.975) 2(-1.4,0.325) 3(-1.4,-0.325) 4(-1.4,-0.975) 5(1.4,-0.975) 6(1.4,-0.325) 7(1.4,0.325) 8(1.4,0.975)
  rect 1.725x2.235 smd paste-3 mask+0.05: 9(0.6,0)
  Top Layer region: -0.4,1.65 0,1.65 0,-1.7 -0.4,-1.7
  silkscreen extent -2.1,1.4 -1.85,1.65, body extent -1.63,-1.65 1.68,1.65, height 1.2
R_0402HD#1 [mm] "Chip Resistor, Body 1.0x0.5mm, IPC High Density"
  rrect50% 0.6x0.6 smd: 1(-0.5,0) 2(0.5,0)
  body extent -0.5,-0.25 0.5,0.26, height 0.33
R_0402HD#2 [mm] "Chip Resistor, Body 1.0x0.5mm, IPC High Density"
  rrect50% 0.6x0.6 smd: 1(-0.5,0)
  rrect50% 0.6x0.6 smd mask+0.03: 2(0.5,0)
  body extent -0.5,-0.25 0.5,0.26, height 0.33
R_0402HD#3 [mm] "Chip Resistor, Body 1.0x0.5mm, IPC High Density"
  rrect50% 0.6x0.6 smd mask+0.03: 1(-0.5,0)
  rrect50% 0.6x0.6 smd: 2(0.5,0)
  body extent -0.5,-0.25 0.5,0.26, height 0.33
R_0402HD#4 [mm] "Chip Resistor, Body 1.0x0.5mm, IPC High Density"
  rrect50% 0.6x0.6 smd: 1(-0.5,0)
  rrect50% 0.6x0.55 smd: 2(0.5,0)
  body extent -0.5,-0.25 0.5,0.26, height 0.33
R_0402hd [mm] "Chip Resistor, Body 1.0x0.5mm, IPC High Density"
  rrect50% 0.6x0.6 smd: 1(-0.5,0) 2(0.5,0)
  body extent -0.5,-0.25 0.5,0.26, height 0.33
R_0603 [mm] "Chip Resistor, Body 1.6x0.8mm, IPC Medium Density"
  rrect50% 0.6x1 smd mask+0.08: 1(-0.75,0)
  rrect50% 0.85x1 smd: 2(0.6,0)
  silkscreen extent -0.1,-0.4 0.1,0.4, body extent -0.85,-0.43 0.7,0.43, height 0.45
R_1206_1MM [mm] "Chip Resistor, Body 3.2x1.6mm, IPC Medium Density, 1 mm height"
  rrect50% 1.3x1.8 smd: 1(-1.45,0) 2(1.45,0)
  silkscreen extent -0.4,-0.8 0.4,0.8, body extent -1.6,-0.85 1.6,0.85, height 1
R_1206_HD [mm] "Chip Resistor, Body 3.2x1.6mm,"
  rrect50% 1.05x1.75 smd: 1(-1.45,0) 2(1.45,0)
  silkscreen extent -0.4,-0.8 0.4,0.8, body extent -1.6,-0.8 1.6,0.81, height 0.55
R_ARR_0804_8 [mm] "resistor array 4res 8 pin"
  rrect50% 0.4x0.65 smd mask+0.05: 1(-0.8,-0.575) 2(-0.8,0.575) 7(0.8,-0.575) 8(0.8,0.575)
  rrect50% 0.3x0.65 smd mask+0.05: 3(-0.25,-0.575) 4(-0.25,0.575) 5(0.25,-0.575) 6(0.25,0.575)
  body extent -1,-0.5 1,0.5, height 0.36
R_ARR_CRA04S08 [mm] "Resistor array 4 vishay CRA04S series"
  rrect30% 0.4x0.5 smd mask+0.05: 1(-0.8,-0.475) 2(-0.8,0.475) 7(0.8,-0.475) 8(0.8,0.475)
  rrect30% 0.3x0.5 smd mask+0.05: 3(-0.25,-0.475) 4(-0.25,0.475) 5(0.25,-0.475) 6(0.25,0.475)
  body extent -1,-0.5 1,0.5, height 0.36
SMA/DO-214AC [mm] "DO-214-AC/SMA; 2 C-Bend Leads; Body 5.3 x 2.6 mm, inc. leads (LxW)"
  rrect50% 2x1.85 smd: 1(-2,0) 2(2,0)
  silkscreen extent 3.5,-0.8 3.5,0.8, body extent -2.6,-1.3 2.6,1.3, height 2.4
SOD123FL [mm] "SOD-123FL; 2 Leads; Body 3.6x 1.65 mm, (LxW)"
  rrect50% 1.25x1.22 smd: 1(-1.45,0) 2(1.45,0)
  silkscreen extent 2.4,-0.6 2.4,0.6, body extent -1.84,-0.85 1.91,0.85, height 1.2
